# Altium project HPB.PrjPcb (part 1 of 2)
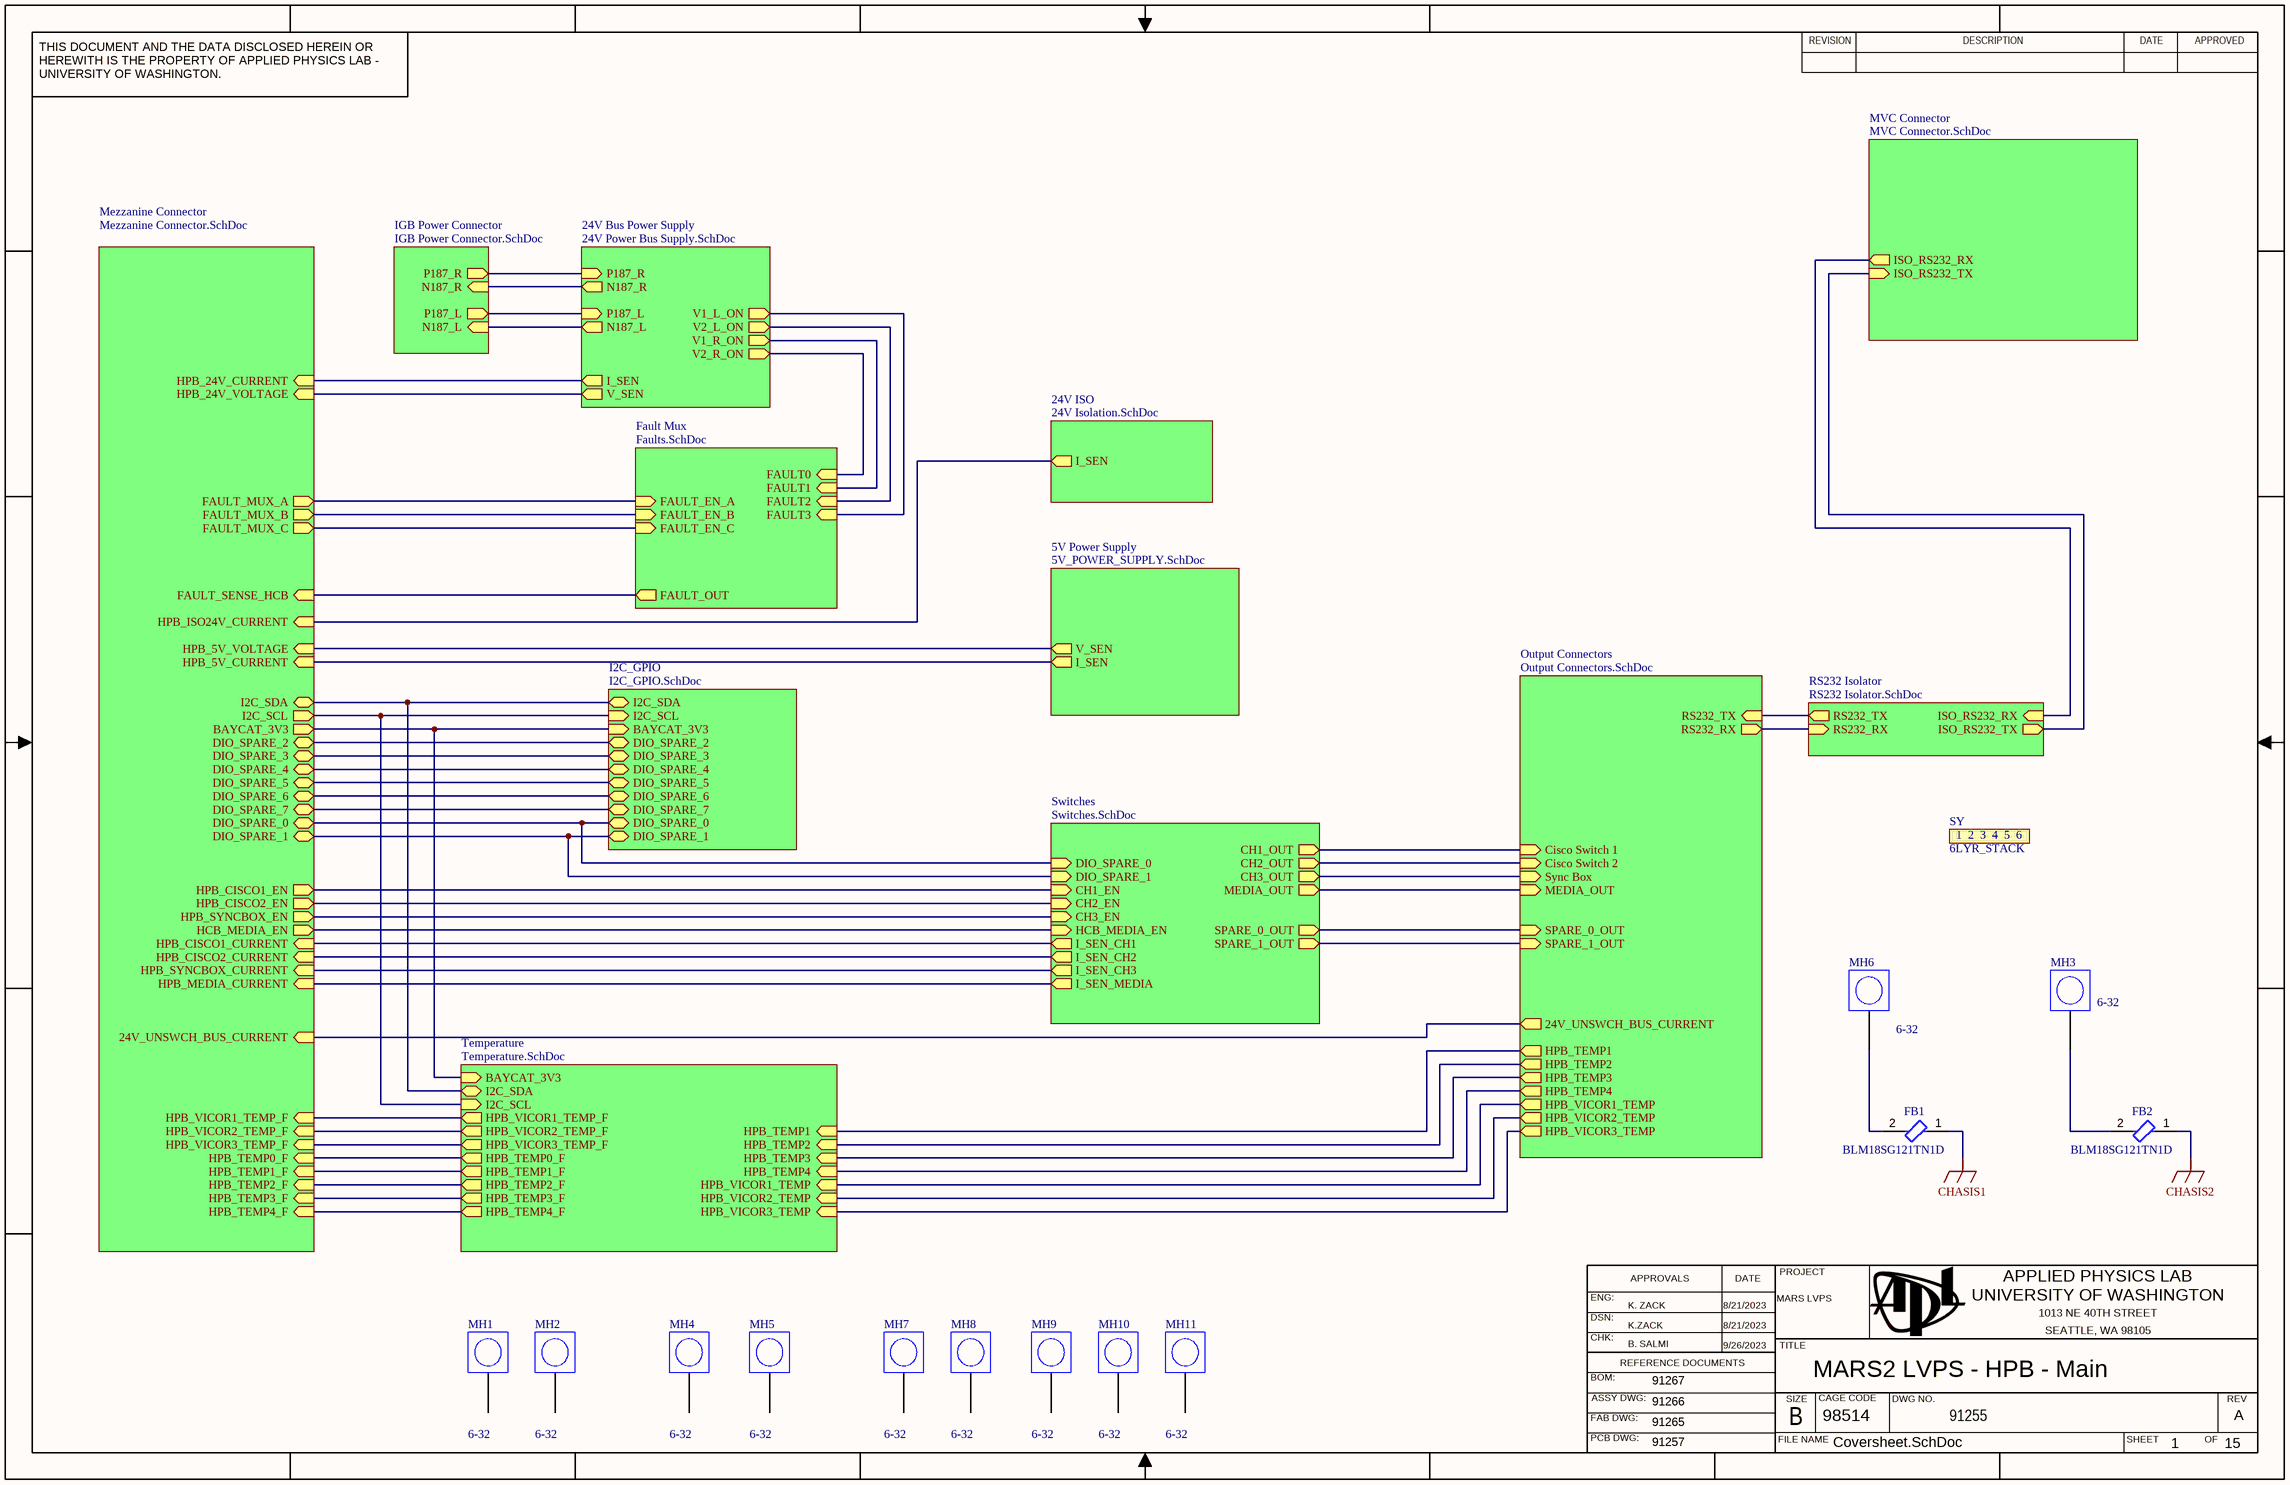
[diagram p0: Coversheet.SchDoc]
Gbl_Cage: 98514; Gbl_CheckedBy: B. SALMI; Gbl_CHK_APP_DATE: 9/26/2023; Gbl_DOC_NO_ASSY_DWG: 91266; Gbl_DOC_NO_BOM: 91267; Gbl_DOC_NO_FAB_DWG: 91265; Gbl_DOC_NO_SCH_DWG: 91255; Gbl_DrawnBy: K.ZACK; Gbl_DSN_APP_DATE: 8/21/2023; Gbl_ENG_APP_DATE: 8/21/2023; Gbl_Engineer: K. ZACK; Gbl_PCB_DWG_NO: 91257; Gbl_Project: MARS LVPS; Gbl_Revision: A
15 sheets, 321 parts. Net scope: hierarchical (ports join the sheet entries above them; power ports are global).
Board file: HPB.PcbDoc
Sheets:
  Coversheet.SchDoc
    IGB Power Connector = IGB Power Connector.SchDoc
    24V Bus Power Supply = 24V Power Bus Supply.SchDoc
      1.024V Comparator V1-Left = 1V024_Comparators.SchDoc
      1.024V Comparator V2-Left = 1V024_Comparators.SchDoc
      1.024V Comparator V1-Right = 1V024_Comparators.SchDoc
      1.024V Comparator V2-Right = 1V024_Comparators.SchDoc
    Mezzanine Connector = Mezzanine Connector.SchDoc
    24V ISO = 24V Isolation.SchDoc
    5V Power Supply = 5V_POWER_SUPPLY.SchDoc
    MVC Connector = MVC Connector.SchDoc
    Output Connectors = Output Connectors.SchDoc
    Fault Mux = Faults.SchDoc
    Switches = Switches.SchDoc
      . = P-CH_SWITCH.SchDoc
      . = P-CH_SWITCH.SchDoc
      . = P-CH_SWITCH.SchDoc
      . = P-CH_SWITCH.SchDoc
      . = P-CH_SWITCH.SchDoc
      . = P-CH_SWITCH.SchDoc
    RS232 Isolator = RS232 Isolator.SchDoc
    Temperature = Temperature.SchDoc
    I2C_GPIO = I2C_GPIO.SchDoc

## Sheet Coversheet.SchDoc: MARS2 LVPS - HPB - Main
size 431 x 279 mm; Organization: ORGANIZATION; Address1: APPLIED PHYSICS LAB; Address2: UNIVERSITY OF WASHINGTON; Address3: 1013 NE 40TH STREET; Address4: SEATTLE, WA 98105; DocumentNumber: 1; Revision: -; SheetNumber: 1; SheetTotal: 15; ENG_APP_DATE: --/--/--; DSN_APP_DATE: --/--/--; CHK_APP_DATE: --/--/--

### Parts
FB1  BLM18SG121TN1D  [FP-BLM18-0_15-t0_5-d1_2-IPC_B]
FB2  BLM18SG121TN1D  [FP-BLM18-0_15-t0_5-d1_2-IPC_B]
MH1  Fastener Size: 6-32  [MH-M3-Footprint-1 - Oversized MARS2]  (hidden comment: MH-MARS2-6-32)  (no BOM)
MH2  Fastener Size: 6-32  [MH-M3-Footprint-1 - Oversized MARS2]  (hidden comment: MH-MARS2-6-32)  (no BOM)
MH3  Fastener Size: 6-32  [MH-M3-Footprint-1 - Oversized MARS2]  (hidden comment: MH-MARS2-6-32)  (no BOM)
MH4  Fastener Size: 6-32  [MH-M3-Footprint-1 - Oversized MARS2]  (hidden comment: MH-MARS2-6-32)  (no BOM)
MH5  Fastener Size: 6-32  [MH-M3-Footprint-1 - Oversized MARS2]  (hidden comment: MH-MARS2-6-32)  (no BOM)
MH6  Fastener Size: 6-32  [MH-M3-Footprint-1 - Oversized MARS2]  (hidden comment: MH-MARS2-6-32)  (no BOM)
MH7  Fastener Size: 6-32  [MH-M3-Footprint-1 - Oversized MARS2]  (hidden comment: MH-MARS2-6-32)  (no BOM)
MH8  Fastener Size: 6-32  [MH-M3-Footprint-1 - Oversized MARS2]  (hidden comment: MH-MARS2-6-32)  (no BOM)
MH9  Fastener Size: 6-32  [MH-M3-Footprint-1 - Oversized MARS2]  (hidden comment: MH-MARS2-6-32)  (no BOM)
MH10  Fastener Size: 6-32  [MH-M3-Footprint-1 - Oversized MARS2]  (hidden comment: MH-MARS2-6-32)  (no BOM)
MH11  Fastener Size: 6-32  [MH-M3-Footprint-1 - Oversized MARS2]  (hidden comment: MH-MARS2-6-32)  (no BOM)
SY  6LYR_STACK  [6LYR_STACK-Footprint-1]

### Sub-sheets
5V Power Supply = 5V_POWER_SUPPLY.SchDoc: V_SEN (out), I_SEN (out)
24V Bus Power Supply = 24V Power Bus Supply.SchDoc: P187_L (in), N187_R (out), P187_R (in), N187_L (out), I_SEN (out), V_SEN (out), V1_L_ON (out), V2_L_ON (out), V1_R_ON (out), V2_R_ON (out)
24V ISO = 24V Isolation.SchDoc: I_SEN (out)
Fault Mux = Faults.SchDoc: FAULT_EN_C (in), FAULT_OUT (out), FAULT_EN_A (in), FAULT0 (in), FAULT_EN_B (in), FAULT1 (in), FAULT2 (in), FAULT3 (in)
I2C_GPIO = I2C_GPIO.SchDoc: I2C_SDA (bidir), I2C_SCL (in), DIO_SPARE_0 (bidir), DIO_SPARE_1 (bidir), DIO_SPARE_2 (bidir), DIO_SPARE_3 (bidir), DIO_SPARE_4 (bidir), DIO_SPARE_5 (bidir), DIO_SPARE_6 (bidir), DIO_SPARE_7 (bidir), BAYCAT_3V3 (in)
IGB Power Connector = IGB Power Connector.SchDoc: N187_R (in), P187_L (out), P187_R (out), N187_L (in)
Mezzanine Connector = Mezzanine Connector.SchDoc: HPB_VICOR1_TEMP_F (in), HPB_CISCO2_CURRENT (in), HPB_VICOR2_TEMP_F (in), HPB_TEMP0_F (in), HPB_24V_CURRENT (in), HPB_TEMP2_F (in), HPB_CISCO1_EN (out), HPB_CISCO1_CURRENT (in), FAULT_MUX_A (out), HPB_CISCO2_EN (out), HPB_SYNCBOX_CURRENT (in), HPB_VICOR3_TEMP_F (in), HPB_ISO24V_CURRENT (in), HPB_TEMP1_F (in), HPB_SYNCBOX_EN (out), FAULT_MUX_B (out), HPB_24V_VOLTAGE (in), HPB_5V_VOLTAGE (in), FAULT_MUX_C (out), HPB_TEMP4_F (in), HPB_5V_CURRENT (in), HPB_TEMP3_F (in), FAULT_SENSE_HCB (in), 24V_UNSWCH_BUS_CURRENT (in), DIO_SPARE_0 (bidir), DIO_SPARE_1 (bidir), DIO_SPARE_2 (bidir), DIO_SPARE_3 (bidir), DIO_SPARE_4 (bidir), DIO_SPARE_5 (bidir), DIO_SPARE_6 (bidir), DIO_SPARE_7 (bidir), HCB_MEDIA_EN (out), I2C_SCL (out), I2C_SDA (bidir), BAYCAT_3V3 (out), HPB_MEDIA_CURRENT (in)
MVC Connector = MVC Connector.SchDoc: ISO_RS232_TX (in), ISO_RS232_RX (out)
Output Connectors = Output Connectors.SchDoc: Cisco Switch 1 (in), Cisco Switch 2 (in), Sync Box (in), RS232_TX (in), RS232_RX (out), HPB_TEMP4 (out), HPB_TEMP1 (out), HPB_TEMP2 (out), HPB_TEMP3 (out), HPB_VICOR1_TEMP (out), HPB_VICOR2_TEMP (out), HPB_VICOR3_TEMP (out), 24V_UNSWCH_BUS_CURRENT (out), MEDIA_OUT (in), SPARE_0_OUT (in), SPARE_1_OUT (in)
RS232 Isolator = RS232 Isolator.SchDoc: RS232_RX (in), RS232_TX (out), ISO_RS232_TX (out), ISO_RS232_RX (in)
Switches = Switches.SchDoc: CH3_OUT (out), CH2_EN (in), CH1_OUT (out), I_SEN_CH2 (out), I_SEN_CH1 (out), CH3_EN (in), I_SEN_CH3 (out), CH1_EN (in), CH2_OUT (out), DIO_SPARE_0 (in), DIO_SPARE_1 (in), HCB_MEDIA_EN (in), MEDIA_OUT (out), SPARE_0_OUT (out), SPARE_1_OUT (out), I_SEN_MEDIA (out)
Temperature = Temperature.SchDoc: HPB_VICOR2_TEMP_F (out), HPB_TEMP0_F (out), HPB_TEMP1_F (out), HPB_VICOR1_TEMP_F (out), HPB_TEMP2_F (out), HPB_TEMP4_F (out), HPB_TEMP3_F (out), HPB_VICOR3_TEMP_F (out), HPB_TEMP4 (in), HPB_TEMP1 (in), HPB_TEMP2 (in), HPB_TEMP3 (in), HPB_VICOR1_TEMP (in), HPB_VICOR2_TEMP (in), HPB_VICOR3_TEMP (in), BAYCAT_3V3 (in), I2C_SDA (bidir), I2C_SCL (in)

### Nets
CHASIS1: FB1.1
CHASIS2: FB2.1
24V_UNSWCH_BUS_CURRENT: sheet Mezzanine Connector/24V_UNSWCH_BUS_CURRENT, sheet Output Connectors/24V_UNSWCH_BUS_CURRENT
BAYCAT_3V3: sheet Mezzanine Connector/BAYCAT_3V3, sheet Temperature/BAYCAT_3V3, sheet I2C_GPIO/BAYCAT_3V3
DIO_SPARE_0: sheet Mezzanine Connector/DIO_SPARE_0, sheet Switches/DIO_SPARE_0, sheet I2C_GPIO/DIO_SPARE_0
DIO_SPARE_1: sheet Mezzanine Connector/DIO_SPARE_1, sheet Switches/DIO_SPARE_1, sheet I2C_GPIO/DIO_SPARE_1
DIO_SPARE_2: sheet Mezzanine Connector/DIO_SPARE_2, sheet I2C_GPIO/DIO_SPARE_2
DIO_SPARE_3: sheet Mezzanine Connector/DIO_SPARE_3, sheet I2C_GPIO/DIO_SPARE_3
DIO_SPARE_4: sheet Mezzanine Connector/DIO_SPARE_4, sheet I2C_GPIO/DIO_SPARE_4
DIO_SPARE_5: sheet Mezzanine Connector/DIO_SPARE_5, sheet I2C_GPIO/DIO_SPARE_5
DIO_SPARE_6: sheet Mezzanine Connector/DIO_SPARE_6, sheet I2C_GPIO/DIO_SPARE_6
DIO_SPARE_7: sheet Mezzanine Connector/DIO_SPARE_7, sheet I2C_GPIO/DIO_SPARE_7
FAULT_MUX_A: sheet Mezzanine Connector/FAULT_MUX_A, sheet Fault Mux/FAULT_EN_A
FAULT_MUX_B: sheet Mezzanine Connector/FAULT_MUX_B, sheet Fault Mux/FAULT_EN_B
FAULT_MUX_C: sheet Mezzanine Connector/FAULT_MUX_C, sheet Fault Mux/FAULT_EN_C
FAULT_SENSE_HCB: sheet Mezzanine Connector/FAULT_SENSE_HCB, sheet Fault Mux/FAULT_OUT
HCB_MEDIA_EN: sheet Mezzanine Connector/HCB_MEDIA_EN, sheet Switches/HCB_MEDIA_EN
HPB_5V_CURRENT: sheet Mezzanine Connector/HPB_5V_CURRENT, sheet 5V Power Supply/I_SEN
HPB_5V_VOLTAGE: sheet Mezzanine Connector/HPB_5V_VOLTAGE, sheet 5V Power Supply/V_SEN
HPB_24V_CURRENT: sheet 24V Bus Power Supply/I_SEN, sheet Mezzanine Connector/HPB_24V_CURRENT
HPB_24V_VOLTAGE: sheet 24V Bus Power Supply/V_SEN, sheet Mezzanine Connector/HPB_24V_VOLTAGE
HPB_CISCO1_CURRENT: sheet Mezzanine Connector/HPB_CISCO1_CURRENT, sheet Switches/I_SEN_CH1
HPB_CISCO1_EN: sheet Mezzanine Connector/HPB_CISCO1_EN, sheet Switches/CH1_EN
HPB_CISCO2_CURRENT: sheet Mezzanine Connector/HPB_CISCO2_CURRENT, sheet Switches/I_SEN_CH2
HPB_CISCO2_EN: sheet Mezzanine Connector/HPB_CISCO2_EN, sheet Switches/CH2_EN
HPB_ISO24V_CURRENT: sheet Mezzanine Connector/HPB_ISO24V_CURRENT, sheet 24V ISO/I_SEN
HPB_MEDIA_CURRENT: sheet Mezzanine Connector/HPB_MEDIA_CURRENT, sheet Switches/I_SEN_MEDIA
HPB_SYNCBOX_CURRENT: sheet Mezzanine Connector/HPB_SYNCBOX_CURRENT, sheet Switches/I_SEN_CH3
HPB_SYNCBOX_EN: sheet Mezzanine Connector/HPB_SYNCBOX_EN, sheet Switches/CH3_EN
HPB_TEMP0: sheet Mezzanine Connector/HPB_TEMP0_F, sheet Temperature/HPB_TEMP0_F
HPB_TEMP1: sheet Mezzanine Connector/HPB_TEMP1_F, sheet Temperature/HPB_TEMP1_F
HPB_TEMP2: sheet Mezzanine Connector/HPB_TEMP2_F, sheet Temperature/HPB_TEMP2_F
HPB_TEMP3: sheet Mezzanine Connector/HPB_TEMP3_F, sheet Temperature/HPB_TEMP3_F
HPB_TEMP4: sheet Mezzanine Connector/HPB_TEMP4_F, sheet Temperature/HPB_TEMP4_F
HPB_VICOR1_TEMP: sheet Mezzanine Connector/HPB_VICOR1_TEMP_F, sheet Temperature/HPB_VICOR1_TEMP_F
HPB_VICOR2_TEMP: sheet Mezzanine Connector/HPB_VICOR2_TEMP_F, sheet Temperature/HPB_VICOR2_TEMP_F
HPB_VICOR3_TEMP: sheet Mezzanine Connector/HPB_VICOR3_TEMP_F, sheet Temperature/HPB_VICOR3_TEMP_F
I2C_SCL: sheet Mezzanine Connector/I2C_SCL, sheet Temperature/I2C_SCL, sheet I2C_GPIO/I2C_SCL
I2C_SDA: sheet Mezzanine Connector/I2C_SDA, sheet Temperature/I2C_SDA, sheet I2C_GPIO/I2C_SDA
N187_L: sheet IGB Power Connector/N187_L, sheet 24V Bus Power Supply/N187_L
N187_R: sheet IGB Power Connector/N187_R, sheet 24V Bus Power Supply/N187_R
OUT: sheet 24V Bus Power Supply/V1_L_ON, sheet Fault Mux/FAULT3
OUT: sheet 24V Bus Power Supply/V2_L_ON, sheet Fault Mux/FAULT2  [a separate net that carries the same name]
OUT: sheet 24V Bus Power Supply/V1_R_ON, sheet Fault Mux/FAULT1  [a separate net that carries the same name]
OUT: sheet 24V Bus Power Supply/V2_R_ON, sheet Fault Mux/FAULT0  [a separate net that carries the same name]
P187_L: sheet IGB Power Connector/P187_L, sheet 24V Bus Power Supply/P187_L
P187_R: sheet IGB Power Connector/P187_R, sheet 24V Bus Power Supply/P187_R
NetFB1_2: FB1.2 MH6.1
NetFB2_2: FB2.2 MH3.1
NetJ5_3: sheet MVC Connector/ISO_RS232_RX, sheet RS232 Isolator/ISO_RS232_RX
NetJ5_6: sheet MVC Connector/ISO_RS232_TX, sheet RS232 Isolator/ISO_RS232_TX
NetJ6_1: sheet Output Connectors/RS232_RX, sheet RS232 Isolator/RS232_RX
NetJ6_3: sheet Output Connectors/RS232_TX, sheet RS232 Isolator/RS232_TX
NetJ8_1: sheet Output Connectors/Cisco Switch 1, sheet Switches/CH1_OUT
NetJ10_1: sheet Output Connectors/HPB_VICOR1_TEMP, sheet Temperature/HPB_VICOR1_TEMP
NetJ10_2: sheet Output Connectors/HPB_VICOR2_TEMP, sheet Temperature/HPB_VICOR2_TEMP
NetJ10_3: sheet Output Connectors/HPB_VICOR3_TEMP, sheet Temperature/HPB_VICOR3_TEMP
NetJ10_4: sheet Output Connectors/HPB_TEMP1, sheet Temperature/HPB_TEMP1
NetJ10_5: sheet Output Connectors/HPB_TEMP2, sheet Temperature/HPB_TEMP2
NetJ10_6: sheet Output Connectors/HPB_TEMP3, sheet Temperature/HPB_TEMP3
NetJ10_7: sheet Output Connectors/HPB_TEMP4, sheet Temperature/HPB_TEMP4
NetJ11_1: sheet Output Connectors/Cisco Switch 2, sheet Switches/CH2_OUT
NetJ13_1: sheet Output Connectors/Sync Box, sheet Switches/CH3_OUT
NetJ15_1: sheet Output Connectors/MEDIA_OUT, sheet Switches/MEDIA_OUT
NetJ16_1: sheet Output Connectors/SPARE_0_OUT, sheet Switches/SPARE_0_OUT
NetJ16_2: sheet Output Connectors/SPARE_1_OUT, sheet Switches/SPARE_1_OUT

Not connected (* = marked no-connect by the designer): MH1 1; MH2 1; MH4 1; MH5 1; MH7 1; MH8 1; MH9 1; MH10 1; MH11 1

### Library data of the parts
FB1 FB2 = CMP-00000-1: Ferrite Beads Multi-Layer 120Ohm 25% 100MHz 3A 0.025Ohm DCR 0603 T/R; DC Resistance (DCR): 25mR; Number of Circuits: 1; Shielding: Unshielded; Material: Steel,Ferrite; Impedance: 120R
MH1-MH11 = CMP-00028-00015-1: MARS2 Project 6-32 Mounting Hole Plated .; Plated: Yes
SY = CMP-00028-00011-3: Layer Indicator for 6 layer board

## Sheet IGB Power Connector.SchDoc: MARS2 LVPS - HPB - IGB PWR CONN
size 431 x 279 mm; Organization: ORGANIZATION; Address1: APPLIED PHYSICS LAB; Address2: UNIVERSITY OF WASHINGTON; Address3: 1013 NE 40TH STREET; Address4: SEATTLE, WA 98105; DocumentNumber: 3; Revision: -; SheetNumber: 3; SheetTotal: 15; ENG_APP_DATE: --/--/--; DSN_APP_DATE: --/--/--; CHK_APP_DATE: --/--/--
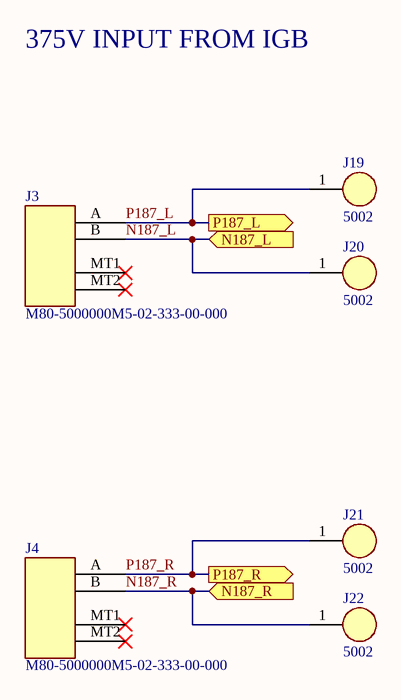
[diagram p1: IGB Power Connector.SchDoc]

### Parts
J3  M80-5000000M5-02-333-00-000  [FP-M80-5000000M5-02-333-0-MFG]
J4  M80-5000000M5-02-333-00-000  [FP-M80-5000000M5-02-333-0-MFG]
J19  5002  [FP-5002-MFG]
J20  5002  [FP-5002-MFG]
J21  5002  [FP-5002-MFG]
J22  5002  [FP-5002-MFG]

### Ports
N187_L (in), N187_R (in), P187_L (out), P187_R (out)

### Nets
N187_L: J3.B J20.1 ; port N187_L
N187_R: J4.B J22.1 ; port N187_R
P187_L: J3.A J19.1 ; port P187_L
P187_R: J4.A J21.1 ; port P187_R

Not connected (* = marked no-connect by the designer): J3 MT1(MNT_1)* MT2(MNT_2)*; J4 MT1(MNT_1)* MT2(MNT_2)*

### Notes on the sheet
- 375V INPUT FROM IGB

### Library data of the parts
J3 J4 = CMP-002-00075-3: Conn Header R/a 2POS 4MM; Manufacturer: Harwin; Number of Positions: 2; Pitch: 4.00mm; Current Rating: 40A; Contact Resistance: 25mR; Voltage Rating: 800V; Gender: Male; Insulation Resistance: 100MR
J19-J22 = CMP-002-00083-3: TEST POINT PC MINI .040D WHITE; Body Material: Bronze

## Sheet 24V Power Bus Supply.SchDoc: MARS2 LVPS - HPB - 375V to 24V PSU
size 431 x 279 mm; Organization: ORGANIZATION; Address1: APPLIED PHYSICS LAB; Address2: UNIVERSITY OF WASHINGTON; Address3: 1013 NE 40TH STREET; Address4: SEATTLE, WA 98105; DocumentNumber: 4; Revision: -; SheetNumber: 4; SheetTotal: 15; ENG_APP_DATE: --/--/--; DSN_APP_DATE: --/--/--; CHK_APP_DATE: --/--/--
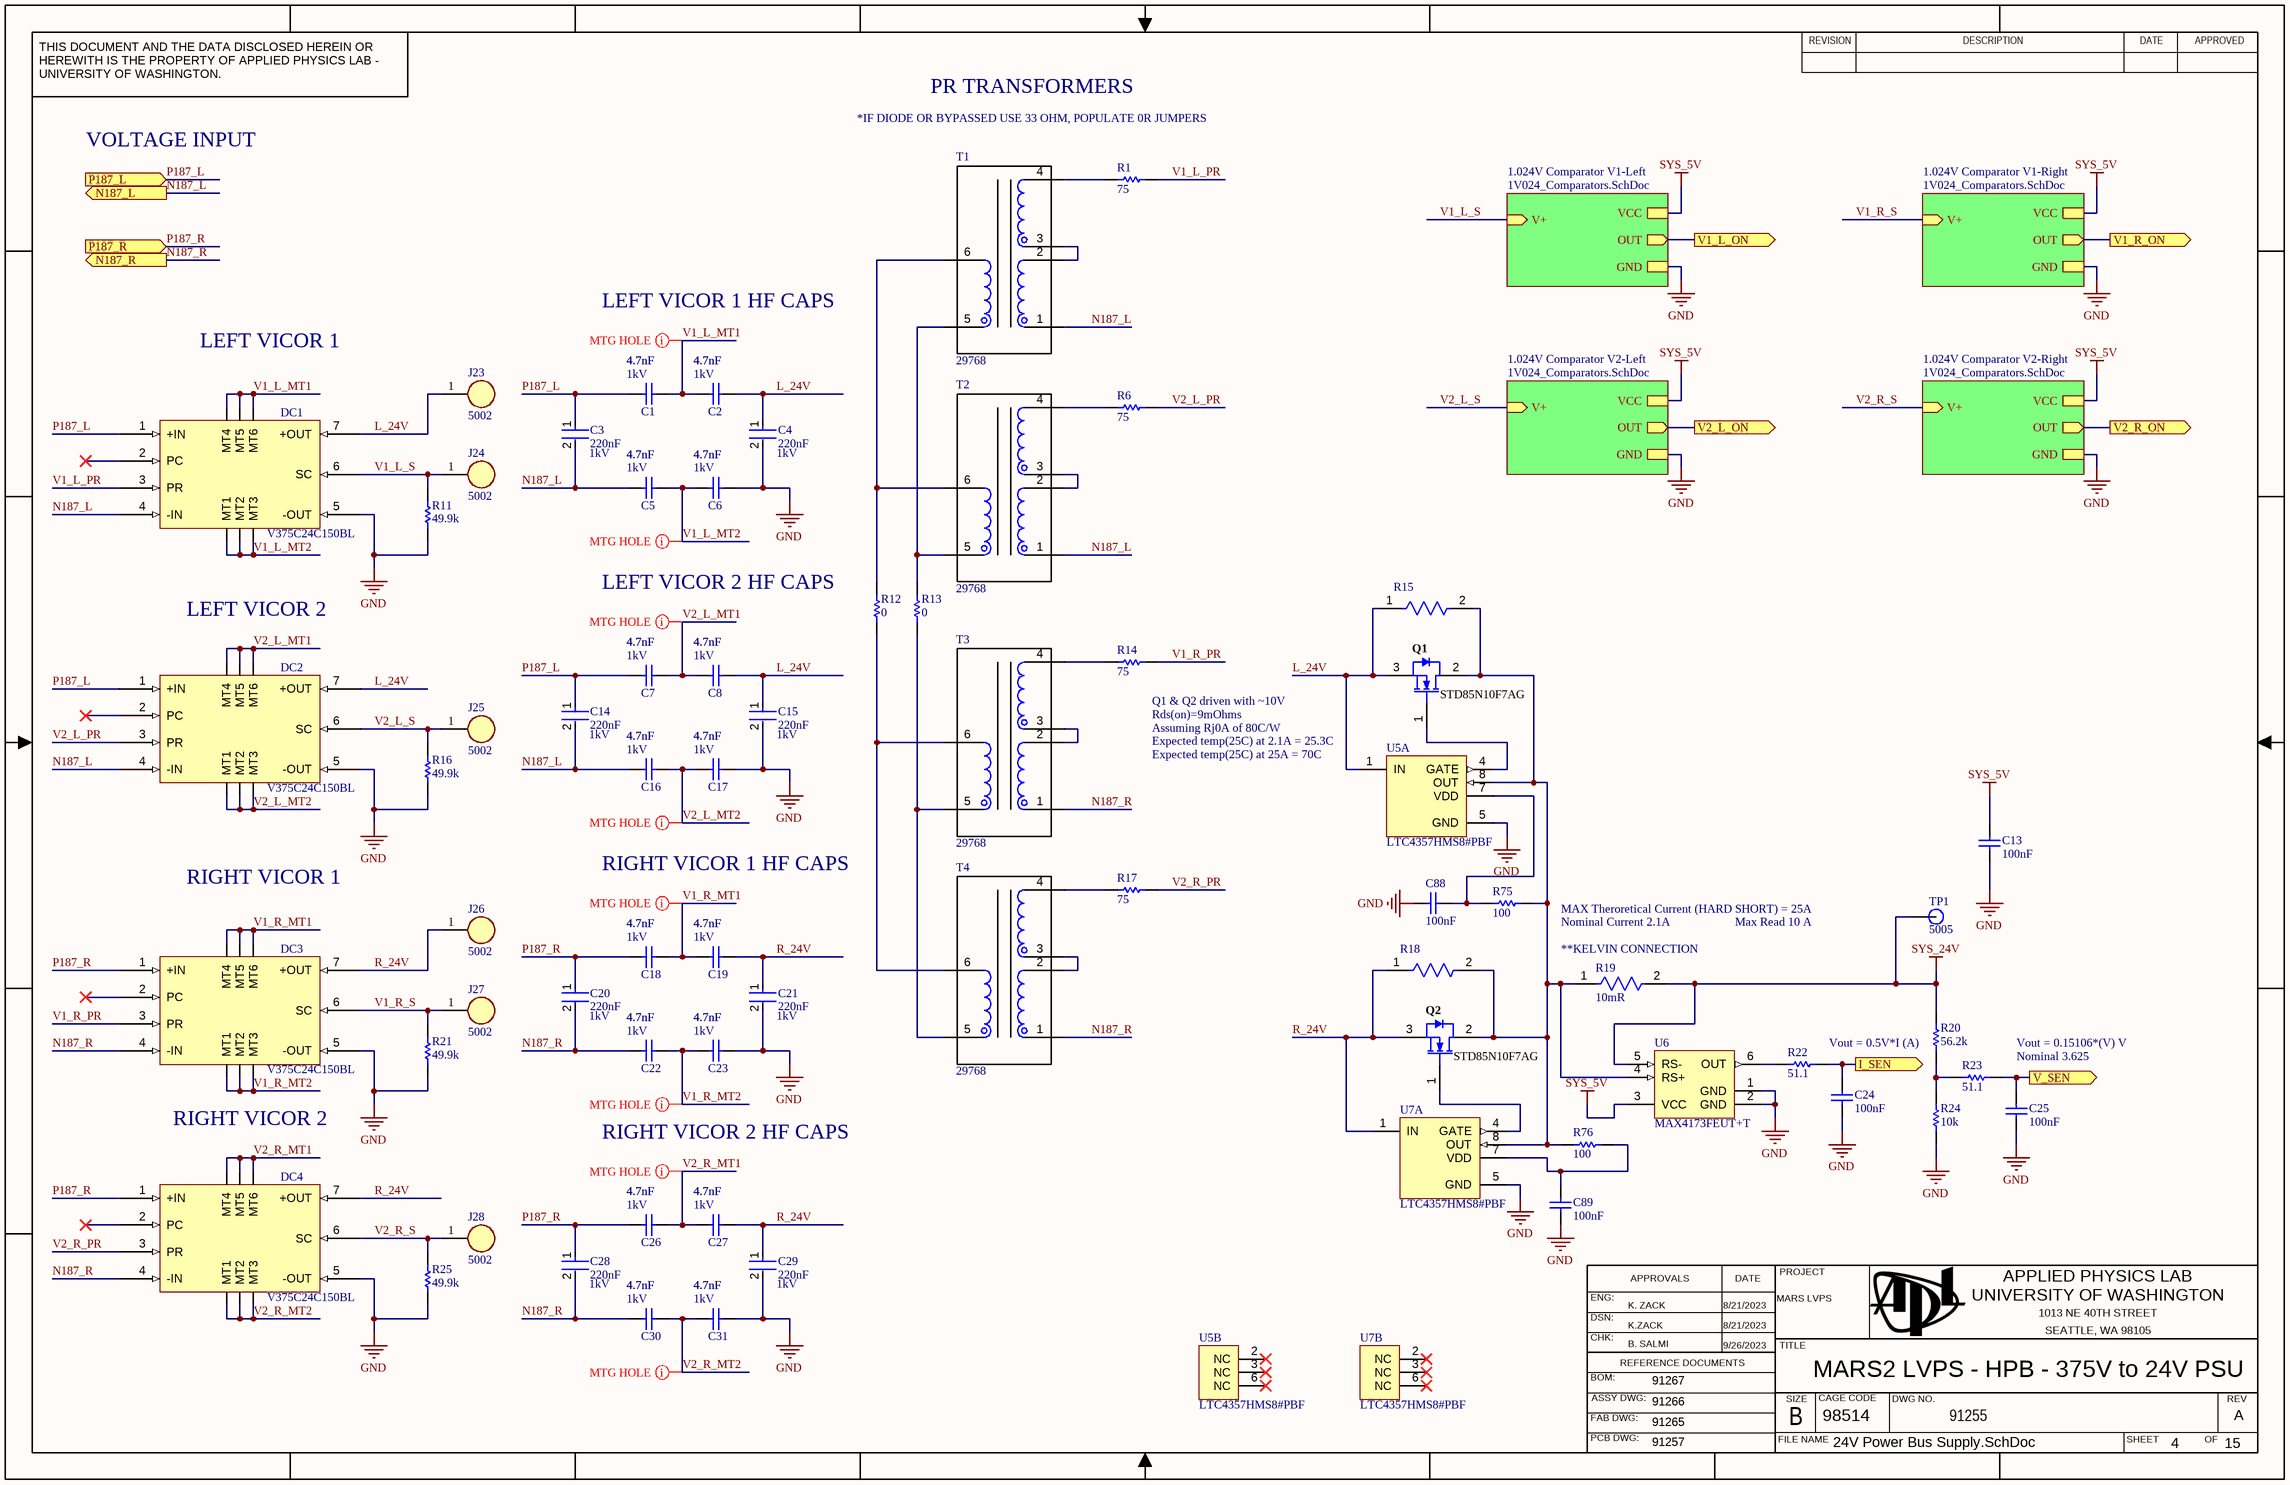
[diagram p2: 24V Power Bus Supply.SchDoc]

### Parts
C1  value 4.7nF  Capacitance: 4.7nF  Voltage Rating: 1kV  [CAPC2013X145X50NL20T25]  (hidden comment: Capacitor 4.7nF 10%, 1kV, X7R, 0805)
C2  value 4.7nF  Capacitance: 4.7nF  Voltage Rating: 1kV  [CAPC2013X145X50NL20T25]  (hidden comment: Capacitor 4.7nF 10%, 1kV, X7R, 0805)
C3  value 220nF  Voltage Rating (DC): 1kV  [FP-RDEUE1+0_5-MFG]  (hidden comment: Capacitor 0.22uF, 20%, 1kV,X7R,Radial)
C4  value 220nF  Voltage Rating (DC): 1kV  [FP-RDEUE1+0_5-MFG]  (hidden comment: Capacitor 0.22uF, 20%, 1kV,X7R,Radial)
C5  value 4.7nF  Capacitance: 4.7nF  Voltage Rating: 1kV  [CAPC2013X145X50NL20T25]  (hidden comment: Capacitor 4.7nF 10%, 1kV, X7R, 0805)
C6  value 4.7nF  Capacitance: 4.7nF  Voltage Rating: 1kV  [CAPC2013X145X50NL20T25]  (hidden comment: Capacitor 4.7nF 10%, 1kV, X7R, 0805)
C7  value 4.7nF  Capacitance: 4.7nF  Voltage Rating: 1kV  [CAPC2013X145X50NL20T25]  (hidden comment: Capacitor 4.7nF 10%, 1kV, X7R, 0805)
C8  value 4.7nF  Capacitance: 4.7nF  Voltage Rating: 1kV  [CAPC2013X145X50NL20T25]  (hidden comment: Capacitor 4.7nF 10%, 1kV, X7R, 0805)
C13  value 100nF  [CAPC1608X90X40NL10T20]  (hidden comment: Capacitor 100 nF +/-10% 50 V 0603)
C14  value 220nF  Voltage Rating (DC): 1kV  [FP-RDEUE1+0_5-MFG]  (hidden comment: Capacitor 0.22uF, 20%, 1kV,X7R,Radial)
C15  value 220nF  Voltage Rating (DC): 1kV  [FP-RDEUE1+0_5-MFG]  (hidden comment: Capacitor 0.22uF, 20%, 1kV,X7R,Radial)
C16  value 4.7nF  Capacitance: 4.7nF  Voltage Rating: 1kV  [CAPC2013X145X50NL20T25]  (hidden comment: Capacitor 4.7nF 10%, 1kV, X7R, 0805)
C17  value 4.7nF  Capacitance: 4.7nF  Voltage Rating: 1kV  [CAPC2013X145X50NL20T25]  (hidden comment: Capacitor 4.7nF 10%, 1kV, X7R, 0805)
C18  value 4.7nF  Capacitance: 4.7nF  Voltage Rating: 1kV  [CAPC2013X145X50NL20T25]  (hidden comment: Capacitor 4.7nF 10%, 1kV, X7R, 0805)
C19  value 4.7nF  Capacitance: 4.7nF  Voltage Rating: 1kV  [CAPC2013X145X50NL20T25]  (hidden comment: Capacitor 4.7nF 10%, 1kV, X7R, 0805)
C20  value 220nF  Voltage Rating (DC): 1kV  [FP-RDEUE1+0_5-MFG]  (hidden comment: Capacitor 0.22uF, 20%, 1kV,X7R,Radial)
C21  value 220nF  Voltage Rating (DC): 1kV  [FP-RDEUE1+0_5-MFG]  (hidden comment: Capacitor 0.22uF, 20%, 1kV,X7R,Radial)
C22  value 4.7nF  Capacitance: 4.7nF  Voltage Rating: 1kV  [CAPC2013X145X50NL20T25]  (hidden comment: Capacitor 4.7nF 10%, 1kV, X7R, 0805)
C23  value 4.7nF  Capacitance: 4.7nF  Voltage Rating: 1kV  [CAPC2013X145X50NL20T25]  (hidden comment: Capacitor 4.7nF 10%, 1kV, X7R, 0805)
C24  value 100nF  [CAPC1608X90X40NL10T20]  (hidden comment: Capacitor 100 nF +/-10% 50 V 0603)
C25  value 100nF  [CAPC1608X90X40NL10T20]  (hidden comment: Capacitor 100 nF +/-10% 50 V 0603)
C26  value 4.7nF  Capacitance: 4.7nF  Voltage Rating: 1kV  [CAPC2013X145X50NL20T25]  (hidden comment: Capacitor 4.7nF 10%, 1kV, X7R, 0805)
C27  value 4.7nF  Capacitance: 4.7nF  Voltage Rating: 1kV  [CAPC2013X145X50NL20T25]  (hidden comment: Capacitor 4.7nF 10%, 1kV, X7R, 0805)
C28  value 220nF  Voltage Rating (DC): 1kV  [FP-RDEUE1+0_5-MFG]  (hidden comment: Capacitor 0.22uF, 20%, 1kV,X7R,Radial)
C29  value 220nF  Voltage Rating (DC): 1kV  [FP-RDEUE1+0_5-MFG]  (hidden comment: Capacitor 0.22uF, 20%, 1kV,X7R,Radial)
C30  value 4.7nF  Capacitance: 4.7nF  Voltage Rating: 1kV  [CAPC2013X145X50NL20T25]  (hidden comment: Capacitor 4.7nF 10%, 1kV, X7R, 0805)
C31  value 4.7nF  Capacitance: 4.7nF  Voltage Rating: 1kV  [CAPC2013X145X50NL20T25]  (hidden comment: Capacitor 4.7nF 10%, 1kV, X7R, 0805)
C88  value 100nF  [CAPC1608X90X40NL10T20]  (hidden comment: Capacitor 100 nF +/-10% 50 V 0603)
C89  value 100nF  [CAPC1608X90X40NL10T20]  (hidden comment: Capacitor 100 nF +/-10% 50 V 0603)
DC1  V375C24C150BL  [V375C24C150BL-Footprint-1]
DC2  V375C24C150BL  [V375C24C150BL-Footprint-1]
DC3  V375C24C150BL  [V375C24C150BL-Footprint-1]
DC4  V375C24C150BL  [V375C24C150BL-Footprint-1]
J23  5002  [FP-5002-MFG]
J24  5002  [FP-5002-MFG]
J25  5002  [FP-5002-MFG]
J26  5002  [FP-5002-MFG]
J27  5002  [FP-5002-MFG]
J28  5002  [FP-5002-MFG]
Q1  STD85N10F7AG  [TO228P970-3N]
Q2  STD85N10F7AG  [TO228P970-3N]
R1  value 75  [RESC1609X50X30ML08T20]  (hidden comment: Resistor 75R0 +/-1% 0603 100 mW)
R6  value 75  [RESC1609X50X30ML08T20]  (hidden comment: Resistor 75R0 +/-1% 0603 100 mW)
R11  value 49.9k  [RESC1608X55X25ML10T15]  (hidden comment: Resistor 49K9 +/-1% 0603 100 mW)
R12  value 0  [RESC1608X55X25ML10T15]  (hidden comment: Resistor 0R +/- 5% 0603 100 mW)
R13  value 0  [RESC1608X55X25ML10T15]  (hidden comment: Resistor 0R +/- 5% 0603 100 mW)
R14  value 75  [RESC1609X50X30ML08T20]  (hidden comment: Resistor 75R0 +/-1% 0603 100 mW)
R15  Resistor 0R01 1% 1206 1W  [FP-WSLP1206-FP_1_65x1_93x-IPC_A]  (value not drawn)
R16  value 49.9k  [RESC1608X55X25ML10T15]  (hidden comment: Resistor 49K9 +/-1% 0603 100 mW)
R17  value 75  [RESC1609X50X30ML08T20]  (hidden comment: Resistor 75R0 +/-1% 0603 100 mW)
R18  Resistor 0R01 1% 1206 1W  [FP-WSLP1206-FP_1_65x1_93x-IPC_A]  (value not drawn)
R19  Resistance: 10mR  [FP-WSLP1206-FP_1_65x1_93x-IPC_A]  (hidden comment: Resistor 0R01 1% 1206 1W)
R20  value 56.2k  [RESC1608X55X25ML10T15]  (hidden comment: Resistor 56K2 +/-1% 0603 100 mW)
R21  value 49.9k  [RESC1608X55X25ML10T15]  (hidden comment: Resistor 49K9 +/-1% 0603 100 mW)
R22  value 51.1  [RESC1609X50X30ML08T20]  (hidden comment: Resistor 51R1 +/-1% 0603 100 mW)
R23  value 51.1  [RESC1609X50X30ML08T20]  (hidden comment: Resistor 51R1 +/-1% 0603 100 mW)
R24  value 10k  [RESC1608X55X25ML10T15]  (hidden comment: Resistor 10k +/-1% 0603 100 mW)
R25  value 49.9k  [RESC1608X55X25ML10T15]  (hidden comment: Resistor 49K9 +/-1% 0603 100 mW)
R75  value 100  [RESC1609X50X30ML08T20]  (hidden comment: Resistor 100R +/-1% 0603 100 mW)
R76  value 100  [RESC1609X50X30ML08T20]  (hidden comment: Resistor 100R +/-1% 0603 100 mW)
T1  29768  [29768-Footprint-1]
T2  29768  [29768-Footprint-1]
T3  29768  [29768-Footprint-1]
T4  29768  [29768-Footprint-1]
TP1  5005  [TestPoint-5005-Footprint-1]
U5  LTC4357HMS8#PBF  [LT-MS8-8_N]  (parts A,B of 2)
U6  MAX4173FEUT+T  [MAXM-U6+1_N]
U7  LTC4357HMS8#PBF  [LT-MS8-8_N]  (parts A,B of 2)

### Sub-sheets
1.024V Comparator V1-Left = 1V024_Comparators.SchDoc: V+ (in), VCC, GND, OUT (out)
1.024V Comparator V1-Right = 1V024_Comparators.SchDoc: V+ (in), VCC, GND, OUT (out)
1.024V Comparator V2-Left = 1V024_Comparators.SchDoc: V+ (in), VCC, GND, OUT (out)
1.024V Comparator V2-Right = 1V024_Comparators.SchDoc: V+ (in), VCC, GND, OUT (out)

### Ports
I_SEN (out), N187_L (out), N187_R (out), P187_L (in), P187_R (in), V1_L_ON (out), V1_R_ON (out), V2_L_ON (out), V2_R_ON (out), V_SEN (out)

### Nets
GND: C4.2 C6.2 C13.1 C15.2 C17.2 C21.2 C23.2 C24.1 C25.1 C29.2 C31.2 C88.1 C89.1 DC1.5(-OUT) DC2.5(-OUT) DC3.5(-OUT) DC4.5(-OUT) R11.2 R16.2 R21.2 R24.1 R25.2 U5.5(GND) U6.1(GND) U6.2(GND) U7.5(GND) ; sheet 1.024V Comparator V1-Left/GND, sheet 1.024V Comparator V2-Left/GND, sheet 1.024V Comparator V1-Right/GND, sheet 1.024V Comparator V2-Right/GND
SYS_5V: C13.2 U6.3(VCC) ; sheet 1.024V Comparator V1-Left/VCC, sheet 1.024V Comparator V2-Left/VCC, sheet 1.024V Comparator V1-Right/VCC, sheet 1.024V Comparator V2-Right/VCC  [project net VCC]
SYS_24V: R19.2 R20.2 TP1.1 U6.5(RS-)
HPB_24V_CURRENT: C24.2 R22.2 ; port I_SEN
HPB_24V_VOLTAGE: C25.2 R23.2 ; port V_SEN
L_24V: C2.2 C4.1 C8.2 C15.1 DC1.7(+OUT) DC2.7(+OUT) J23.1 Q1.3(S) R15.1 U5.1(IN)
N187_L: C3.2 C5.1 C14.2 C16.1 DC1.4(-IN) DC2.4(-IN) T1.1 T2.1 ; port N187_L
N187_R: C20.2 C22.1 C28.2 C30.1 DC3.4(-IN) DC4.4(-IN) T3.1 T4.1 ; port N187_R
OUT: port V1_L_ON, sheet 1.024V Comparator V1-Left/OUT
OUT: port V2_L_ON, sheet 1.024V Comparator V2-Left/OUT  [a separate net that carries the same name]
OUT: port V1_R_ON, sheet 1.024V Comparator V1-Right/OUT  [a separate net that carries the same name]
OUT: port V2_R_ON, sheet 1.024V Comparator V2-Right/OUT  [a separate net that carries the same name]
P187_L: C1.1 C3.1 C7.1 C14.1 DC1.1(+IN) DC2.1(+IN) ; port P187_L
P187_R: C18.1 C20.1 C26.1 C28.1 DC3.1(+IN) DC4.1(+IN) ; port P187_R
R_24V: C19.2 C21.1 C27.2 C29.1 DC3.7(+OUT) DC4.7(+OUT) J26.1 Q2.3(S) R18.1 U7.1(IN)
V1_L_MT1: C1.2 C2.1 DC1.MT4 DC1.MT5 DC1.MT6
V1_L_MT2: C5.2 C6.1 DC1.MT1 DC1.MT2 DC1.MT3
V1_L_PR: DC1.3(PR) R1.2
V1_L_S: DC1.6(SC) J24.1 R11.1 ; sheet 1.024V Comparator V1-Left/V+
V1_R_MT1: C18.2 C19.1 DC3.MT4 DC3.MT5 DC3.MT6
V1_R_MT2: C22.2 C23.1 DC3.MT1 DC3.MT2 DC3.MT3
V1_R_PR: DC3.3(PR) R14.2
V1_R_S: DC3.6(SC) J27.1 R21.1 ; sheet 1.024V Comparator V1-Right/V+
V2_L_MT1: C7.2 C8.1 DC2.MT4 DC2.MT5 DC2.MT6
V2_L_MT2: C16.2 C17.1 DC2.MT1 DC2.MT2 DC2.MT3
V2_L_PR: DC2.3(PR) R6.2
V2_L_S: DC2.6(SC) J25.1 R16.1 ; sheet 1.024V Comparator V2-Left/V+
V2_R_MT1: C26.2 C27.1 DC4.MT4 DC4.MT5 DC4.MT6
V2_R_MT2: C30.2 C31.1 DC4.MT1 DC4.MT2 DC4.MT3
V2_R_PR: DC4.3(PR) R17.2
V2_R_S: DC4.6(SC) J28.1 R25.1 ; sheet 1.024V Comparator V2-Right/V+
NetC88_2: C88.2 R75.1 U5.7(VDD)
NetC89_2: C89.2 R76.2 U7.7(VDD)
NetQ1_1: Q1.1(G) U5.4(GATE)
NetQ1_2: Q1.2(D) Q2.2(D) R15.2 R18.2 R19.1 R75.2 R76.1 U5.8(OUT) U6.4(RS+) U7.8(OUT)
NetQ2_1: Q2.1(G) U7.4(GATE)
NetR1_1: R1.1 T1.4
NetR6_1: R6.1 T2.4
NetR12_1: R12.1 T1.6 T2.6
NetR12_2: R12.2 T3.6 T4.6
NetR13_1: R13.1 T1.5 T2.5
NetR13_2: R13.2 T3.5 T4.5
NetR14_1: R14.1 T3.4
NetR17_1: R17.1 T4.4
NetR20_1: R20.1 R23.1 R24.2
NetR22_1: R22.1 U6.6(OUT)
NetT1_2: T1.2 T1.3
NetT2_2: T2.2 T2.3
NetT3_2: T3.2 T3.3
NetT4_2: T4.2 T4.3

Not connected (* = marked no-connect by the designer): DC1 2(PC)*; DC2 2(PC)*; DC3 2(PC)*; DC4 2(PC)*; U5 2(NC)* 3(NC)* 6(NC)*; U7 2(NC)* 3(NC)* 6(NC)*

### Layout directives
net class MTG Hole: V1_L_MT1, V1_L_MT2, V1_R_MT1, V1_R_MT2, V2_L_MT1, V2_L_MT2, V2_R_MT1, V2_R_MT2

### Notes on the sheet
- PR TRANSFORMERS
- VOLTAGE INPUT
- *IF DIODE OR BYPASSED USE 33 OHM, POPULATE 0R JUMPERS
- LEFT VICOR 1
- LEFT VICOR 1 HF CAPS
- LEFT VICOR 2
- LEFT VICOR 2 HF CAPS
- (near R14) Q1 & Q2 driven with
  0V
- (near R14) Rds(on)=9mOhms
- (near U5) Expected temp(25C) at 2.1A = 25.3C
- (near U5) Expected temp(25C) at 25A = 70C
- Assuming Rj0A of 80C/W
- RIGHT VICOR 1
- RIGHT VICOR 1 HF CAPS
- (near R19) **KELVIN CONNECTION
- (near R75) MAX Theroretical Current (HARD SHORT) = 25A
- Nominal Current 2.1A
- Max Read 10 A
- (near R20) Vout = 0.5V*I (A)
- Nominal 3.625
- Vout = 0.15106*(V) V
- RIGHT VICOR 2
- RIGHT VICOR 2 HF CAPS

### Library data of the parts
C1 C2 C5-C8 C16-C19 C22 C23 C26 C27 C30 C31 = CMP-001-00109-9: 0805 Arcshield HV 4.7nF Ceramic Multilayer Cap; 1000VDC; +125C; X7R Dielec; +/-10%; Decade: 1nF
C3 C4 C14 C15 C20 C21 C28 C29 = CMP-001-00084-11: Cap Ceramic 0.22uF 1000V X7R 20% Radial 5mm 125°C Bulk; Manufacturer PN: RDER73A224MUB1H03B; Lead Diameter: 0.5mm; Lead/Base Style: Straight; Decade: 100nF
C13 C24 C25 C88 C89 = CMP-001-00017-14: Chip Capacitor, 100 nF, +/- 10%, 50 V, 0603 (1608 Metric); Voltage Rating: 50V; Capacitor Type: Ceramic
DC1-DC4 = CMP-019-00060-1: 375C Series 150 W Single Output 24 V DC-DC Converter; Isolation Voltage: 3kV; Voltage - Output 1: 24V; Number of Outputs: 1; Max Output Current: 6.25A; Max Input Voltage: 425V; Max Power Dissipation: 150W; Efficiency: 86.5%; Isolation: Isolated; Min Input Voltage: 250V
J23-J28 = CMP-002-00083-3: as J19 on sheet IGB Power Connector
Q1 Q2 = CMP-013-00055-1: Trans MOSFET N-CH 100V 70A Automotive 3-Pin(2+Tab) DPAK T/R; Input Capacitance: 3.1nF; Max Power Dissipation: 85W; Rds On Max: 10mR
R1 R6 R14 R17 = CMP-009-01151-1: Chip Resistor, 75 Ohm, +/- 1%, 0.1 W, -55 to 155 degC, 0603 (1608 Metric); Voltage Rating: 75V; Power: 100mW; Decade: 10
R11 R16 R21 R25 = CMP-009-01001-3: Chip Resistor, 49.9k Ohm, +/- 1%, 0.1 W, -55 to 155 degC, 0603 (1608 Metric); Power: 100mW; Voltage Rating: 75V; Decade: 10k
R12 R13 = CMP-009-00006-6: Chip Resistor, 0 Ohm, 0.1 W, -55 to 155 degC, 0603 (1608 Metric); Voltage Rating: 50V; Power: 100mW
R15 R18 = CMP-009-01193-1: Res Metal Strip 1206 0.01 Ohm 1% 1W ±75ppm/°C Molded SMD SMD Embossed Plastic T/R; Manufacturer PN: WSLP1206R0100FEA; Resistance: 10mR
R19 = CMP-009-01193-1: Res Metal Strip 1206 0.01 Ohm 1% 1W ±75ppm/°C Molded SMD SMD Embossed Plastic T/R; Manufacturer PN: WSLP1206R0100FEA
R20 = CMP-009-01006-3: Chip Resistor, 56.2k Ohm, +/- 1%, 0.1 W, -55 to 155 degC, 0603 (1608 Metric); Voltage Rating: 75V; Power: 100mW; Decade: 10k
R22 R23 = CMP-009-01135-1: Chip Resistor, 51.1 Ohm, +/- 1%, 0.1 W, -55 to 155 degC, 0603 (1608 Metric); Voltage Rating: 75V; Power: 100mW; Decade: 10
R24 = CMP-009-00017-7: Chip Resistor, 10 KOhm, +/- 1%, 01 W, -55 to 155 degC, 0603 (1608 Metric); Voltage Rating: 50V; Power: 100mW
R75 R76 = CMP-009-01066-2: Chip Resistor, 100 Ohm, +/- 1%, 0.1 W, -55 to 155 degC, 0603 (1608 Metric); Voltage Rating: 75V; Power: 100mW
T1-T4 = CMP-012-00000-1: 3 W 101 to 187 uH 40 to 50 mOhm DCR PR Bus Toroidal Inductor; Manufacturer: Vicor; Lead/Base Style: PC Pin
TP1 = CMP-001-0000-5: PC TEST POINT COMPACT RED; Inside Diameter: 1.78mm; Hole Diameter: 1.6mm
U5 U7 = CMP-004-00036-2: OR Controller N+1 ORing Controller N-Channel N:1 8-MSOP; Min Supply Voltage: 9V; Max Output Current: 210uA; Max Supply Voltage: 80V
U6 = CMP-014-00007-3: MAX4173 Series 28 V 1.4 MHz Voltage Current Sense Operational Amplifier - SOT-23; Nominal Supply Current: 420uA; Common Mode Rejection Ratio: 90dB; Min Supply Voltage: 3V; Input Bias Current: 700uA; -3db Bandwidth: 1.4MHz; Max Supply Voltage: 28V; Max Supply Current: 1mA; Input Offset Voltage (Vos): 300uV; Gain: 50V/V

## Sheet 1V024_Comparators.SchDoc: MARS2 LVPS - HPB - Vicor Fault Mon
size 431 x 279 mm; Organization: ORGANIZATION; Address1: APPLIED PHYSICS LAB; Address2: UNIVERSITY OF WASHINGTON; Address3: 1013 NE 40TH STREET; Address4: SEATTLE, WA 98105; Revision: -; SheetNumber: 5; SheetTotal: 15; ENG_APP_DATE: --/--/--; DSN_APP_DATE: --/--/--; CHK_APP_DATE: --/--/--
Used 4 times, as channels 24V Bus Power Supply/1.024V Comparator V1-Left, 24V Bus Power Supply/1.024V Comparator V2-Left, 24V Bus Power Supply/1.024V Comparator V1-Right, 24V Bus Power Supply/1.024V Comparator V2-Right. Parts and nets are listed once, with the designators drawn on the sheet.
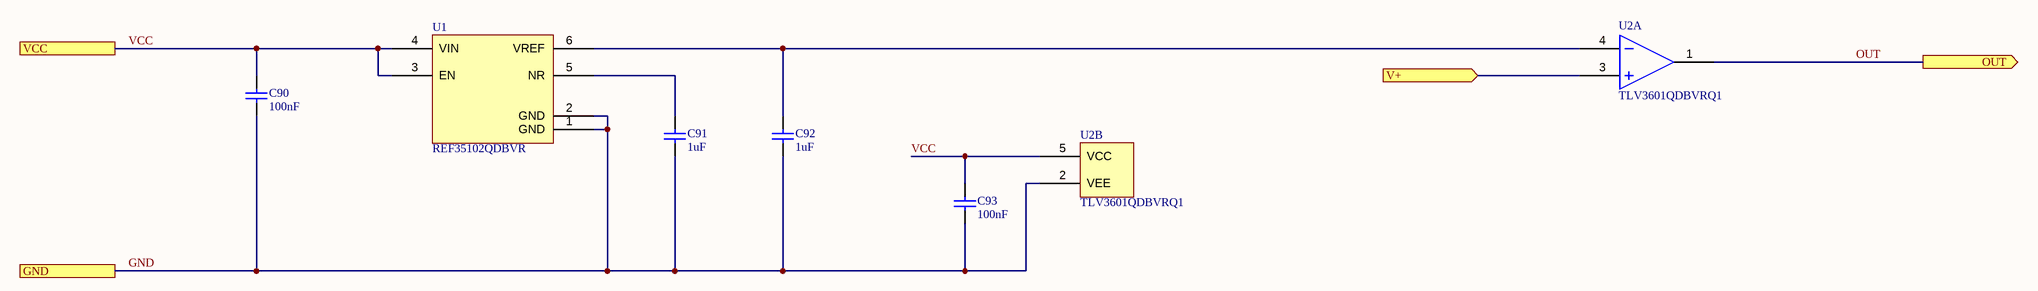
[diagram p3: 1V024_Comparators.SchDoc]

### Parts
C90  value 100nF  [CAPC1608X90X40NL10T20]  (hidden comment: Capacitor 100 nF +/-10% 50 V 0603)
C91  value 1uF  [CAPC3225X270X30ML30]  (hidden comment: Capacitor 1uF 10%, 50V, X7R, 1210)
C92  value 1uF  [CAPC3225X270X30ML30]  (hidden comment: Capacitor 1uF 10%, 50V, X7R, 1210)
C93  value 100nF  [CAPC1608X90X40NL10T20]  (hidden comment: Capacitor 100 nF +/-10% 50 V 0603)
U1  REF35102QDBVR  [SOT95P280X145-6M]
U2  TLV3601QDBVRQ1  [SOT95P280X145-5M]  (parts A,B of 2)

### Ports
GND, OUT (out), V+ (in), VCC

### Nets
GND: C90.1 C91.1 C92.1 C93.1 U1.1(GND) U1.2(GND) U2.2(VEE) ; port GND
OUT: U2.1(OUT) ; port OUT
V+: U2.3(IN+) ; port V+
VCC: C90.2 C93.2 U1.3(EN) U1.4(VIN) U2.5(VCC) ; port VCC
NetC91_2: C91.2 U1.5(NR)
NetC92_2: C92.2 U1.6(VREF) U2.4(IN-)

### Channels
24V Bus Power Supply/1.024V Comparator V1-Left: designators end in A; ports GND=GND OUT=OUT V+=V1_L_S VCC=VCC
24V Bus Power Supply/1.024V Comparator V2-Left: designators end in B; ports GND=GND OUT=OUT V+=V2_L_S VCC=VCC
24V Bus Power Supply/1.024V Comparator V1-Right: designators end in C; ports GND=GND OUT=OUT V+=V1_R_S VCC=VCC
24V Bus Power Supply/1.024V Comparator V2-Right: designators end in D; ports GND=GND OUT=OUT V+=V2_R_S VCC=VCC

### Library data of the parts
C90 C93 = CMP-001-00017-14: as C13 on sheet 24V Power Bus Supply
C91 C92 = CMP-001-00181-9: Chip Capacitor, 1uF, 10%, 50 V, X7R 1210 (3225 Metric); Capacitor Type: Ceramic
U1 = CMP-019-00086-3: 650-nA quiescent current, 12-ppm/°C drift, ultra-low-power precision voltage reference, 1.024V, 6-SOT-23 -40 to 125
U2 = CMP-014-00029-3: Automotive, 2.5-ns, high-speed, rail-to-rail comparator with push-pull outputs 5-SOT-23 -40 to 125

## Sheet Mezzanine Connector.SchDoc: MARS2 LVPS - HPB - Mezzanine Conn
size 431 x 279 mm; Organization: ORGANIZATION; Address1: APPLIED PHYSICS LAB; Address2: UNIVERSITY OF WASHINGTON; Address3: 1013 NE 40TH STREET; Address4: SEATTLE, WA 98105; DocumentNumber: 2; Revision: -; SheetNumber: 2; SheetTotal: 15; ENG_APP_DATE: --/--/--; DSN_APP_DATE: --/--/--; CHK_APP_DATE: --/--/--
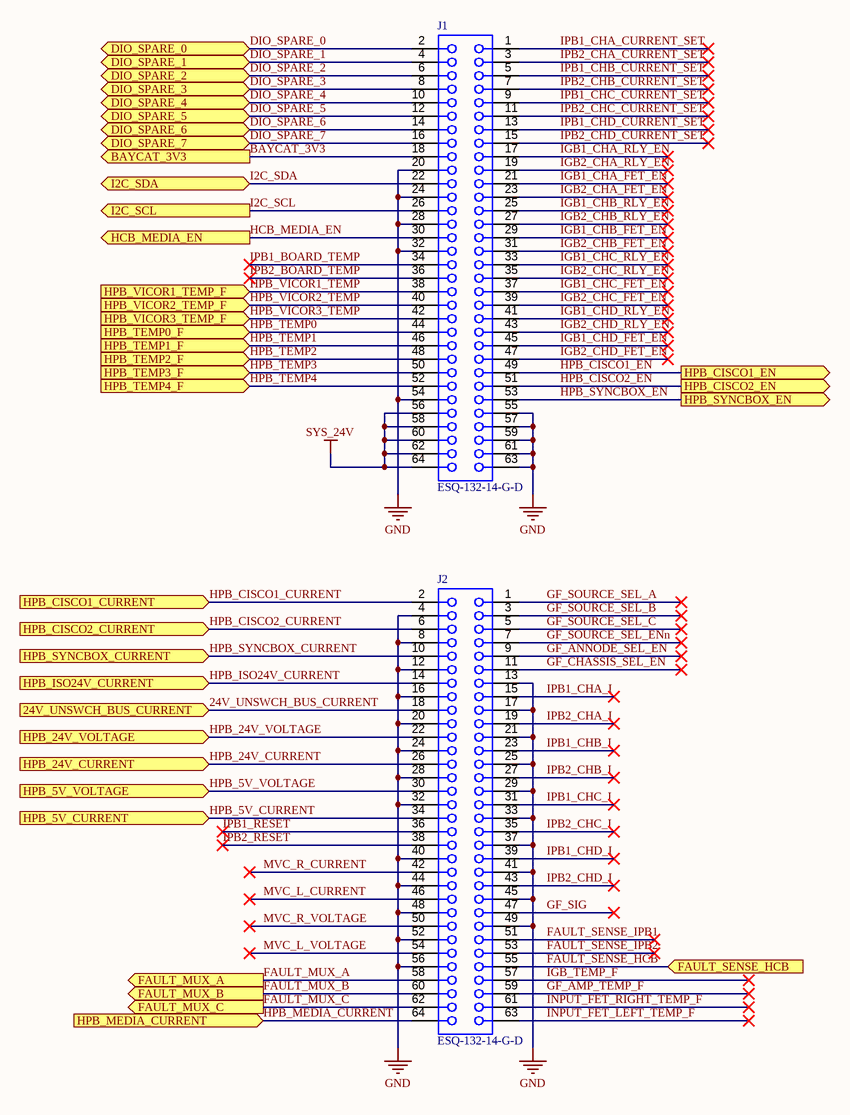
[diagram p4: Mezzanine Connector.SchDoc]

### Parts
J1  ESQ-132-14-G-D  [SMTC-ESQ-132-14-X-D]
J2  ESQ-132-14-G-D  [SMTC-ESQ-132-14-X-D]

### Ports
24V_UNSWCH_BUS_CURRENT (in), BAYCAT_3V3 (out), DIO_SPARE_0 (bidir), DIO_SPARE_1 (bidir), DIO_SPARE_2 (bidir), DIO_SPARE_3 (bidir), DIO_SPARE_4 (bidir), DIO_SPARE_5 (bidir), DIO_SPARE_6 (bidir), DIO_SPARE_7 (bidir), FAULT_MUX_A (out), FAULT_MUX_B (out), FAULT_MUX_C (out), FAULT_SENSE_HCB (in), HCB_MEDIA_EN (out), HPB_5V_CURRENT (in), HPB_5V_VOLTAGE (in), HPB_24V_CURRENT (in), HPB_24V_VOLTAGE (in), HPB_CISCO1_CURRENT (in), HPB_CISCO1_EN (out), HPB_CISCO2_CURRENT (in), HPB_CISCO2_EN (out), HPB_ISO24V_CURRENT (in), HPB_MEDIA_CURRENT (in), HPB_SYNCBOX_CURRENT (in), HPB_SYNCBOX_EN (out), HPB_TEMP0_F (in), HPB_TEMP1_F (in), HPB_TEMP2_F (in), HPB_TEMP3_F (in), HPB_TEMP4_F (in), HPB_VICOR1_TEMP_F (in), HPB_VICOR2_TEMP_F (in), HPB_VICOR3_TEMP_F (in), I2C_SCL (out), I2C_SDA (bidir)

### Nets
GND: J1.20 J1.24 J1.28 J1.32 J1.54 J1.55 J1.57 J1.59 J1.61 J1.63 J2.4 J2.8 J2.12 J2.13 J2.16 J2.17 J2.20 J2.21 J2.24 J2.25 J2.28 J2.29 J2.32 J2.33 J2.37 J2.40 J2.41 J2.44 J2.45 J2.48 J2.49 J2.52 J2.56
SYS_24V: J1.56 J1.58 J1.60 J1.62 J1.64
24V_UNSWCH_BUS_CURRENT: J2.18 ; port 24V_UNSWCH_BUS_CURRENT
BAYCAT_3V3: J1.18 ; port BAYCAT_3V3
DIO_SPARE_0: J1.2 ; port DIO_SPARE_0
DIO_SPARE_1: J1.4 ; port DIO_SPARE_1
DIO_SPARE_2: J1.6 ; port DIO_SPARE_2
DIO_SPARE_3: J1.8 ; port DIO_SPARE_3
DIO_SPARE_4: J1.10 ; port DIO_SPARE_4
DIO_SPARE_5: J1.12 ; port DIO_SPARE_5
DIO_SPARE_6: J1.14 ; port DIO_SPARE_6
DIO_SPARE_7: J1.16 ; port DIO_SPARE_7
FAULT_MUX_A: J2.58 ; port FAULT_MUX_A
FAULT_MUX_B: J2.60 ; port FAULT_MUX_B
FAULT_MUX_C: J2.62 ; port FAULT_MUX_C
FAULT_SENSE_HCB: J2.55 ; port FAULT_SENSE_HCB
FAULT_SENSE_IPB1: J2.51
FAULT_SENSE_IPB2: J2.53
GF_AMP_TEMP_F: J2.59
GF_ANNODE_SEL_EN: J2.9
GF_CHASSIS_SEL_EN: J2.11
GF_SIG: J2.47
GF_SOURCE_SEL_A: J2.1
GF_SOURCE_SEL_B: J2.3
GF_SOURCE_SEL_C: J2.5
GF_SOURCE_SEL_ENn: J2.7
HCB_MEDIA_EN: J1.30 ; port HCB_MEDIA_EN
HPB_5V_CURRENT: J2.34 ; port HPB_5V_CURRENT
HPB_5V_VOLTAGE: J2.30 ; port HPB_5V_VOLTAGE
HPB_24V_CURRENT: J2.26 ; port HPB_24V_CURRENT
HPB_24V_VOLTAGE: J2.22 ; port HPB_24V_VOLTAGE
HPB_CISCO1_CURRENT: J2.2 ; port HPB_CISCO1_CURRENT
HPB_CISCO1_EN: J1.49 ; port HPB_CISCO1_EN
HPB_CISCO2_CURRENT: J2.6 ; port HPB_CISCO2_CURRENT
HPB_CISCO2_EN: J1.51 ; port HPB_CISCO2_EN
HPB_ISO24V_CURRENT: J2.14 ; port HPB_ISO24V_CURRENT
HPB_MEDIA_CURRENT: J2.64 ; port HPB_MEDIA_CURRENT
HPB_SYNCBOX_CURRENT: J2.10 ; port HPB_SYNCBOX_CURRENT
HPB_SYNCBOX_EN: J1.53 ; port HPB_SYNCBOX_EN
HPB_TEMP0: J1.44 ; port HPB_TEMP0_F
HPB_TEMP1: J1.46 ; port HPB_TEMP1_F
HPB_TEMP2: J1.48 ; port HPB_TEMP2_F
HPB_TEMP3: J1.50 ; port HPB_TEMP3_F
HPB_TEMP4: J1.52 ; port HPB_TEMP4_F
HPB_VICOR1_TEMP: J1.38 ; port HPB_VICOR1_TEMP_F
HPB_VICOR2_TEMP: J1.40 ; port HPB_VICOR2_TEMP_F
HPB_VICOR3_TEMP: J1.42 ; port HPB_VICOR3_TEMP_F
I2C_SCL: J1.26 ; port I2C_SCL
I2C_SDA: J1.22 ; port I2C_SDA
IGB1_CHA_FET_EN: J1.21
IGB1_CHA_RLY_EN: J1.17
IGB1_CHB_FET_EN: J1.29
IGB1_CHB_RLY_EN: J1.25
IGB1_CHC_FET_EN: J1.37
IGB1_CHC_RLY_EN: J1.33
IGB1_CHD_FET_EN: J1.45
IGB1_CHD_RLY_EN: J1.41
IGB2_CHA_FET_EN: J1.23
IGB2_CHA_RLY_EN: J1.19
IGB2_CHB_FET_EN: J1.31
IGB2_CHB_RLY_EN: J1.27
IGB2_CHC_FET_EN: J1.39
IGB2_CHC_RLY_EN: J1.35
IGB2_CHD_FET_EN: J1.47
IGB2_CHD_RLY_EN: J1.43
IGB_TEMP_F: J2.57
INPUT_FET_LEFT_TEMP_F: J2.63
INPUT_FET_RIGHT_TEMP_F: J2.61
IPB1_BOARD_TEMP: J1.34
IPB1_CHA_CURRENT_SET: J1.1
IPB1_CHA_I: J2.15
IPB1_CHB_CURRENT_SET: J1.5
IPB1_CHB_I: J2.23
IPB1_CHC_CURRENT_SET: J1.9
IPB1_CHC_I: J2.31
IPB1_CHD_CURRENT_SET: J1.13
IPB1_CHD_I: J2.39
IPB1_RESET: J2.36
IPB2_BOARD_TEMP: J1.36
IPB2_CHA_CURRENT_SET: J1.3
IPB2_CHA_I: J2.19
IPB2_CHB_CURRENT_SET: J1.7
IPB2_CHB_I: J2.27
IPB2_CHC_CURRENT_SET: J1.11
IPB2_CHC_I: J2.35
IPB2_CHD_CURRENT_SET: J1.15
IPB2_CHD_I: J2.43
IPB2_RESET: J2.38
MVC_L_CURRENT: J2.46
MVC_L_VOLTAGE: J2.54
MVC_R_CURRENT: J2.42
MVC_R_VOLTAGE: J2.50

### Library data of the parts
J1 J2 = CMP-002-00093-2: Conn Elevated Socket SKT 64 POS 2.54mm Solder ST Top Entry Thru-Hole Tube; Voltage Rating (AC): 550V; Current Rating: 6.9A; Number of Contacts: 64; Row Spacing: 0.1inch; Connector Type: Receptacle; Contact Resistance: 10mR

## Sheet 24V Isolation.SchDoc: MARS2 LVPS - HPB - ISO 24V
size 431 x 279 mm; Organization: ORGANIZATION; Address1: APPLIED PHYSICS LAB; Address2: UNIVERSITY OF WASHINGTON; Address3: 1013 NE 40TH STREET; Address4: SEATTLE, WA 98105; DocumentNumber: 5; Revision: -; SheetNumber: 6; SheetTotal: 15; ENG_APP_DATE: --/--/--; DSN_APP_DATE: --/--/--; CHK_APP_DATE: --/--/--
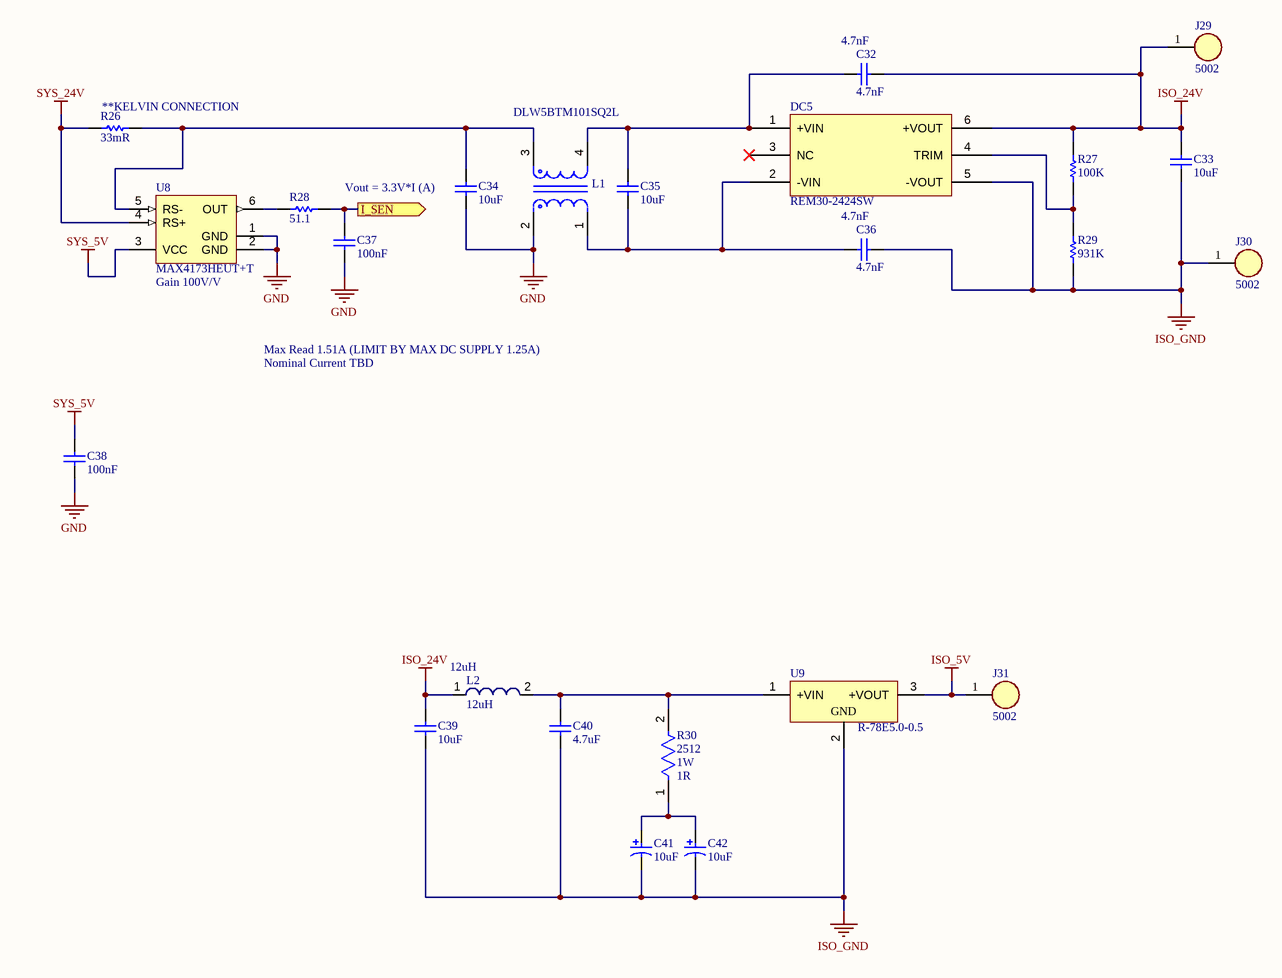
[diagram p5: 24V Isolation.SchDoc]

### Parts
C32  value 4.7nF  Capacitance: 4.7nF  [CAPC2013X145X50NL20T25]  (hidden comment: Capacitor 4.7nF 10%, 1kV, X7R, 0805)
C33  value 10uF  [CAPC3225X270X30ML30]  (hidden comment: Capacitor 10uF 10%, 50V, X7R, 1210)
C34  value 10uF  [CAPC3225X270X30ML30]  (hidden comment: Capacitor 10uF 10%, 50V, X7R, 1210)
C35  value 10uF  [CAPC3225X270X30ML30]  (hidden comment: Capacitor 10uF 10%, 50V, X7R, 1210)
C36  value 4.7nF  Capacitance: 4.7nF  [CAPC2013X145X50NL20T25]  (hidden comment: Capacitor 4.7nF 10%, 1kV, X7R, 0805)
C37  value 100nF  [CAPC1608X90X40NL10T20]  (hidden comment: Capacitor 100 nF +/-10% 50 V 0603)
C38  value 100nF  [CAPC1608X90X40NL10T20]  (hidden comment: Capacitor 100 nF +/-10% 50 V 0603)
C39  value 10uF  [CAPC3225X270X30ML30]  (hidden comment: Capacitor 10uF 10%, 50V, X7R, 1210)
C40  value 4.7uF  [CAPC3225X270X30ML30]  (hidden comment: Capacitor 4.7uF 10%, 50V, X7R, 1210)
C41  value 10uF  [KEMT-D-7343-31-2_L]  (hidden comment: T491D106K050AT)
C42  value 10uF  [KEMT-D-7343-31-2_L]  (hidden comment: T491D106K050AT)
DC5  REM30-2424SW  [REM30-2424SW-Footprint-1]
J29  5002  [FP-5002-MFG]
J30  5002  [FP-5002-MFG]
J31  5002  [FP-5002-MFG]
L1  DLW5BTM101SQ2L  [FP-DLW5BT-MFG]
L2  value 12uH  Inductance: 12uH  [WE-LQS 8040]  (hidden comment: 74404084120)
R26  Resistance: 33mR  [RESC3216X70X50NL05T20]  (hidden comment: Resistor 0R033 1% 1206 1W)
R27  value 100K  [RESC1609X50X30ML08T20]  (hidden comment: Resistor 100K +/-1% 0603 100 mW)
R28  value 51.1  [RESC1609X50X30ML08T20]  (hidden comment: Resistor 51R1 +/-1% 0603 100 mW)
R29  value 931K  [RESC1609X50X30ML08T20]  (hidden comment: Resistor 931K +/-1% 0603 100 mW)
R30  Case Code (Imperial): 2512  Power Rating: 1W  Resistance: 1R  [FP-CRCW2512-e3-MFG]  (hidden comment: Resistor 1R0 1% 2512 1W)
U8  MAX4173HEUT+T  [MAXM-U6+1_N]
U9  R-78E5.0-0.5  [REPO-R-78E-0.5-3_V]

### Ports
I_SEN (out)

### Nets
GND: C34.1 C37.1 C38.1 L1.2 U8.1(GND) U8.2(GND)
ISO_5V: J31.1 U9.3(+VOUT)
ISO_24V: C32.2 C33.2 C39.2 DC5.6(+VOUT) J29.1 L2.1 R27.2
ISO_GND: C33.1 C36.2 C39.1 C40.1 C41.2 C42.2 DC5.5(-VOUT) J30.1 R29.1 U9.2(GND)
SYS_5V: C38.2 U8.3(VCC)  [project net VCC]
SYS_24V: R26.2 U8.4(RS+)
HPB_ISO24V_CURRENT: C37.2 R28.2 ; port I_SEN
NetC32_1: C32.1 C35.2 DC5.1(+VIN) L1.4
NetC34_2: C34.2 L1.3 R26.1 U8.5(RS-)
NetC35_1: C35.1 C36.1 DC5.2(-VIN) L1.1
NetC40_2: C40.2 L2.2 R30.2 U9.1(+VIN)
NetC41_1: C41.1 C42.1 R30.1
NetDC5_4: DC5.4(TRIM) R27.1 R29.2
NetR28_1: R28.1 U8.6(OUT)

Not connected (* = marked no-connect by the designer): DC5 3(NC)*

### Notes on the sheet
- (near R26) **KELVIN CONNECTION
- Vout = 3.3V*I (A)
- (near U8) Gain 100V/V
- Nominal Current TBD
- Max Read 1.51A (LIMIT BY MAX DC SUPPLY 1.25A)

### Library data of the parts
C32 C36 = CMP-001-00109-9: as C1 on sheet 24V Power Bus Supply
C33-C35 C39 = CMP-001-00184-9: Chip Capacitor, 10uF, 10%, 50 V, X7R 1210 (3225 Metric); Capacitor Type: Ceramic
C37 C38 = CMP-001-00017-14: as C13 on sheet 24V Power Bus Supply
C40 = CMP-001-00183-9: Chip Capacitor, 4.7uF, 10%, 50 V, X7R 1210 (3225 Metric); Capacitor Type: Ceramic; Decade: 1uF
C41 C42 = CMP-001-00088-9: 10uF Solid MnO2 Tantalum Electrolytic Capacitor; 50 V dc +/-10%; T491 Series; Manufacturer: KEMET; Voltage: 50V; Tolerance: 10%; Life (Hours): 2000Hour; Dissipation Factor: 6%; Ripple Current: 433mA; Leakage Current: 5uA; ESR (Equivalent Series Resistance): 800mR; Polarity: Polar
DC5 = CMP-019-00061-2: 30W DC/DC-Converter 'MEDLINE' 2"x1" 5kV reg 4: 1; Voltage - Input (Max): 36V; Current - Output (Max): 1.25A; Voltage - Input (Min): 9V; Voltage - Output 1: 24V; Efficiency: 89%
J29-J31 = CMP-002-00083-3: as J19 on sheet IGB Power Connector
L1 = CMP-006-00027-1: Ind Common Mode Choke Wirewound 100 Ohm 100MHz 6A 2020 Embossed T/R; Number of Lines: 2; DC Resistance (DCR): 13mR; Impedance: 100R; Voltage Rating (DC): 50V; Shielding: Unshielded; Tolerance: 40%
L2 = CMP-006-00026-2: WE-LQS Series; Shielded Wire-wound SMD Inductor 12; RMS Current (Irms): 2.8A; Saturation Current: 3.8A; DC Resistance (DCR): 40mR; Tolerance: 20%; Core Material: Ferrite; Self Resonant Frequency: 21MHz; Test Frequency: 100kHz
R26 = CMP-009-01194-1: Res Thick Film 1206 0.033 Ohm 1% 1W ±75ppm/C Pad SMD Automotive T/R; Manufacturer PN: ERJ-8CWFR033V; Temperature Coefficient: 75ppm/°C
R27 = CMP-009-01065-1: Chip Resistor, 100k Ohm, +/- 1%, 0.1 W, -55 to 155 degC, 0603 (1608 Metric); Power: 100mW; Voltage Rating: 75V
R28 = CMP-009-01135-1: as R22 on sheet 24V Power Bus Supply
R29 = CMP-009-01062-1: Chip Resistor, 931k Ohm, +/- 1%, 0.1 W, -55 to 155 degC, 0603 (1608 Metric); Power: 100mW; Decade: 100k; Voltage Rating: 75V
R30 = CMP-009-01195-2: Res Thick Film 2512 1 Ohm 1% 1W ±100ppm/°C Molded SMD SMD; Manufacture PN: CRCW25121R00FKEG; Voltage Rating: 500V
U8 = CMP-014-00008-1: MAX4173 Series 28 V 1.2 MHz Voltage Current Sense Operational Amplifier - SOT-23; Gain: 100V/V; Common Mode Rejection Ratio: 90dB; Max Supply Voltage: 28V; -3db Bandwidth: 1.2MHz; Supply Current: 420uA; Min Supply Voltage: 3V; Input Bias Current: 700uA
U9 = CMP-019-00059-1: 0.5A DC/DC-Converter 'INNOLINE' SIP3 reg; V. In: 7-28; V. Out: 5.0; mA. Out: 500; Max Power Dissipation: 3W; Max Input Voltage: 28V; Current - Output 1: 500mA; Power Rating: 2.5W; Output Voltage: 5V; Min Input Voltage: 7V; Isolation: Non-Isolated; Number of Outputs: 1; Efficiency: 92%; Output Type: Fixed

## Sheet 5V_POWER_SUPPLY.SchDoc: MARS2 LVPS - HPB - 5V PSU
size 431 x 279 mm; Organization: ORGANIZATION; Address1: APPLIED PHYSICS LAB; Address2: UNIVERSITY OF WASHINGTON; Address3: 1013 NE 40TH STREET; Address4: SEATTLE, WA 98105; DocumentNumber: 6; Revision: -; SheetNumber: 7; SheetTotal: 15; ENG_APP_DATE: --/--/--; DSN_APP_DATE: --/--/--; CHK_APP_DATE: --/--/--
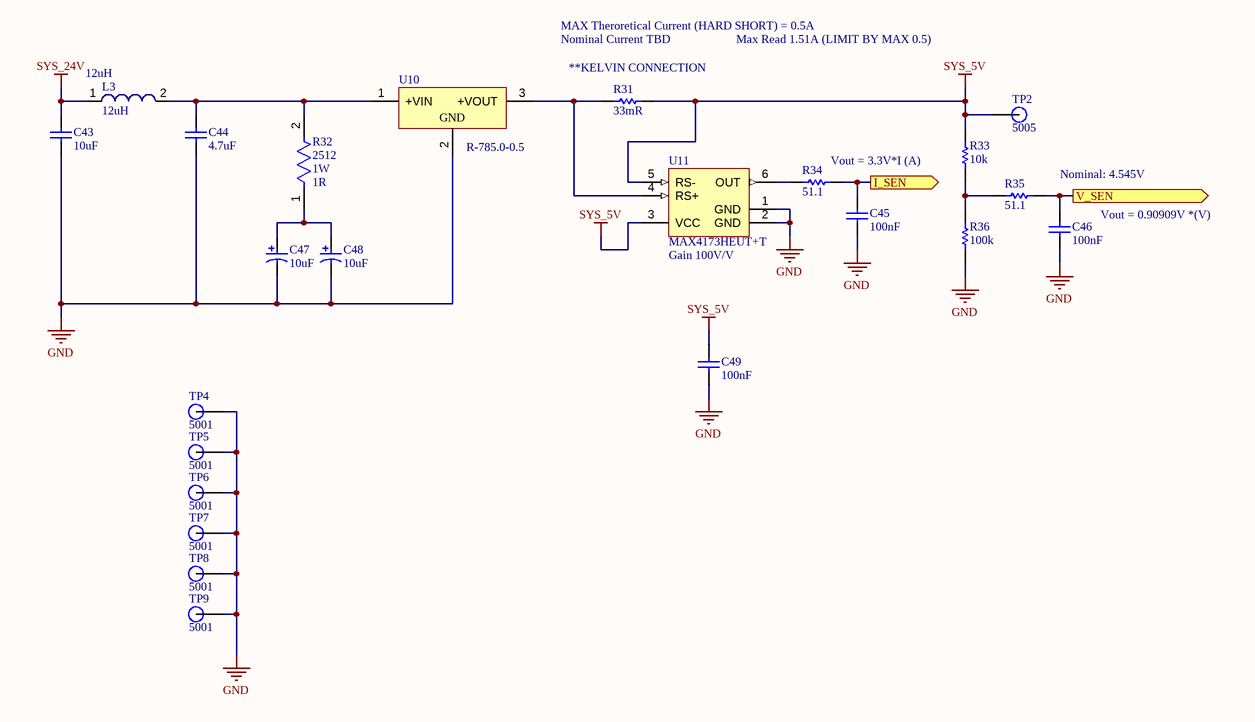
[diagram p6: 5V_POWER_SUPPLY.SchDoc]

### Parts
C43  value 10uF  [CAPC3225X270X30ML30]  (hidden comment: Capacitor 10uF 10%, 50V, X7R, 1210)
C44  value 4.7uF  [CAPC3225X270X30ML30]  (hidden comment: Capacitor 4.7uF 10%, 50V, X7R, 1210)
C45  value 100nF  [CAPC1608X90X40NL10T20]  (hidden comment: Capacitor 100 nF +/-10% 50 V 0603)
C46  value 100nF  [CAPC1608X90X40NL10T20]  (hidden comment: Capacitor 100 nF +/-10% 50 V 0603)
C47  value 10uF  [KEMT-D-7343-31-2_L]  (hidden comment: T491D106K050AT)
C48  value 10uF  [KEMT-D-7343-31-2_L]  (hidden comment: T491D106K050AT)
C49  value 100nF  [CAPC1608X90X40NL10T20]  (hidden comment: Capacitor 100 nF +/-10% 50 V 0603)
L3  value 12uH  Inductance: 12uH  [WE-LQS 8040]  (hidden comment: 74404084120)
R31  Resistance: 33mR  [RESC3216X70X50NL05T20]  (hidden comment: Resistor 0R033 1% 1206 1W)
R32  Case Code (Imperial): 2512  Power Rating: 1W  Resistance: 1R  [FP-CRCW2512-e3-MFG]  (hidden comment: Resistor 1R0 1% 2512 1W)
R33  value 10k  [RESC1608X55X25ML10T15]  (hidden comment: Resistor 10k +/-1% 0603 100 mW)
R34  value 51.1  [RESC1609X50X30ML08T20]  (hidden comment: Resistor 51R1 +/-1% 0603 100 mW)
R35  value 51.1  [RESC1609X50X30ML08T20]  (hidden comment: Resistor 51R1 +/-1% 0603 100 mW)
R36  value 100k  [RESC1608X55X25ML10T15]  (hidden comment: Resistor 100k +/-1% 0603 100 mW)
TP2  5005  [TestPoint-5005-Footprint-1]
TP4  5001  [FP-5001-MFG]
TP5  5001  [FP-5001-MFG]
TP6  5001  [FP-5001-MFG]
TP7  5001  [FP-5001-MFG]
TP8  5001  [FP-5001-MFG]
TP9  5001  [FP-5001-MFG]
U10  R-785.0-0.5  [REPO-R-78XX-3_V]
U11  MAX4173HEUT+T  [MAXM-U6+1_N]

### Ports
I_SEN (out), V_SEN (out)

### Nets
GND: C43.1 C44.1 C45.1 C46.1 C47.2 C48.2 C49.1 R36.1 TP4.1 TP5.1 TP6.1 TP7.1 TP8.1 TP9.1 U10.2(GND) U11.1(GND) U11.2(GND)
SYS_5V: C49.2 R31.1 R33.2 TP2.1 U11.3(VCC) U11.5(RS-)  [project net VCC]
SYS_24V: C43.2 L3.1
HPB_5V_CURRENT: C45.2 R34.2 ; port I_SEN
HPB_5V_VOLTAGE: C46.2 R35.2 ; port V_SEN
NetC44_2: C44.2 L3.2 R32.2 U10.1(+VIN)
NetC47_1: C47.1 C48.1 R32.1
NetR31_2: R31.2 U10.3(+VOUT) U11.4(RS+)
NetR33_1: R33.1 R35.1 R36.2
NetR34_1: R34.1 U11.6(OUT)

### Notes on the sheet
- MAX Theroretical Current (HARD SHORT) = 0.5A
- Nominal Current TBD
- Max Read 1.51A (LIMIT BY MAX 0.5)
- (near R31) **KELVIN CONNECTION
- (near R34) Vout = 3.3V*I (A)
- Nominal: 4.545V
- (near U11) Gain 100V/V
- (near C46) Vout = 0.90909V *(V)

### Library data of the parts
C43 = CMP-001-00184-9: as C33 on sheet 24V Isolation
C44 = CMP-001-00183-9: as C40 on sheet 24V Isolation
C45 C46 C49 = CMP-001-00017-14: as C13 on sheet 24V Power Bus Supply
C47 C48 = CMP-001-00088-9: as C41 on sheet 24V Isolation
L3 = CMP-006-00026-2: as L2 on sheet 24V Isolation
R31 = CMP-009-01194-1: as R26 on sheet 24V Isolation
R32 = CMP-009-01195-2: as R30 on sheet 24V Isolation
R33 = CMP-009-00017-7: as R24 on sheet 24V Power Bus Supply
R34 R35 = CMP-009-01135-1: as R22 on sheet 24V Power Bus Supply
R36 = CMP-009-00023-6: Chip Resistor, 100 KOhm, +/- 1%, 0.1 W, -55 to 155 degC, 0603 (1608 Metric); Voltage Rating: 50V; Power: 100mW
TP2 = CMP-001-0000-5: as TP1 on sheet 24V Power Bus Supply
TP4-TP9 = CMP-001-0002-3: TEST POINT PC MINI .040D BLACK
U10 = CMP-019-00062-2: 0.5A DC/DC-Converter 'INNOLINE' SIP3 reg; V. In: 6.5-32; V. Out: 5.0; mA. Out: 500; Nominal Input Voltage: 24V; Max Power Dissipation: 3W; Efficiency: 94%; Min Input Voltage (DC): 6.5V; Current - Output 1: 500mA; Isolation: Non-Isolated; Max Input Voltage: 32V; Switching Frequency: 380kHz; Max Output Power: 2.5W; Max Output Voltage: 5V; Isolation Voltage: 2kV
U11 = CMP-014-00008-1: as U8 on sheet 24V Isolation

## Sheet MVC Connector.SchDoc: MARS2 LVPS - HPB - MVC Conn
size 431 x 279 mm; Organization: ORGANIZATION; Address1: APPLIED PHYSICS LAB; Address2: UNIVERSITY OF WASHINGTON; Address3: 1013 NE 40TH STREET; Address4: SEATTLE, WA 98105; DocumentNumber: 7; Revision: -; SheetNumber: 8; SheetTotal: 15; ENG_APP_DATE: --/--/--; DSN_APP_DATE: --/--/--; CHK_APP_DATE: --/--/--
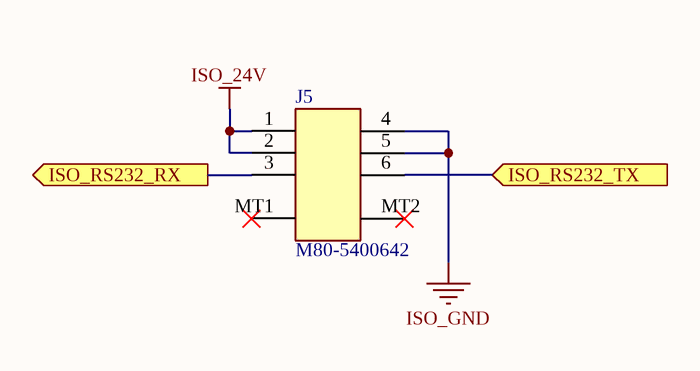
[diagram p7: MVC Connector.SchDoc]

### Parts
J5  M80-5400642  [FP-M80-5400642-MFG]

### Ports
ISO_RS232_RX (out), ISO_RS232_TX (in)

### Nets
ISO_24V: J5.1 J5.2
ISO_GND: J5.4 J5.5
NetJ5_3: J5.3 ; port ISO_RS232_RX
NetJ5_6: J5.6 ; port ISO_RS232_TX

Not connected (* = marked no-connect by the designer): J5 MT1* MT2*

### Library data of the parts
J5 = CMP-002-00076-5: Conn Header R/a 6POS 2MM; Manufacturer: Harwin; Current Rating: 3A; Contact Resistance: 25mR; Gender: Male; Max Voltage Rating (AC): 120V; Voltage Rating: 800V; Number of Contacts: 6; Insulation Resistance: 100MR

## Sheet Output Connectors.SchDoc: MARS2 LVPS - HPB - Output Connectors
size 431 x 279 mm; Organization: ORGANIZATION; Address1: APPLIED PHYSICS LAB; Address2: UNIVERSITY OF WASHINGTON; Address3: 1013 NE 40TH STREET; Address4: SEATTLE, WA 98105; DocumentNumber: 10; Revision: -; SheetNumber: 12; SheetTotal: 15; ENG_APP_DATE: --/--/--; DSN_APP_DATE: --/--/--; CHK_APP_DATE: --/--/--
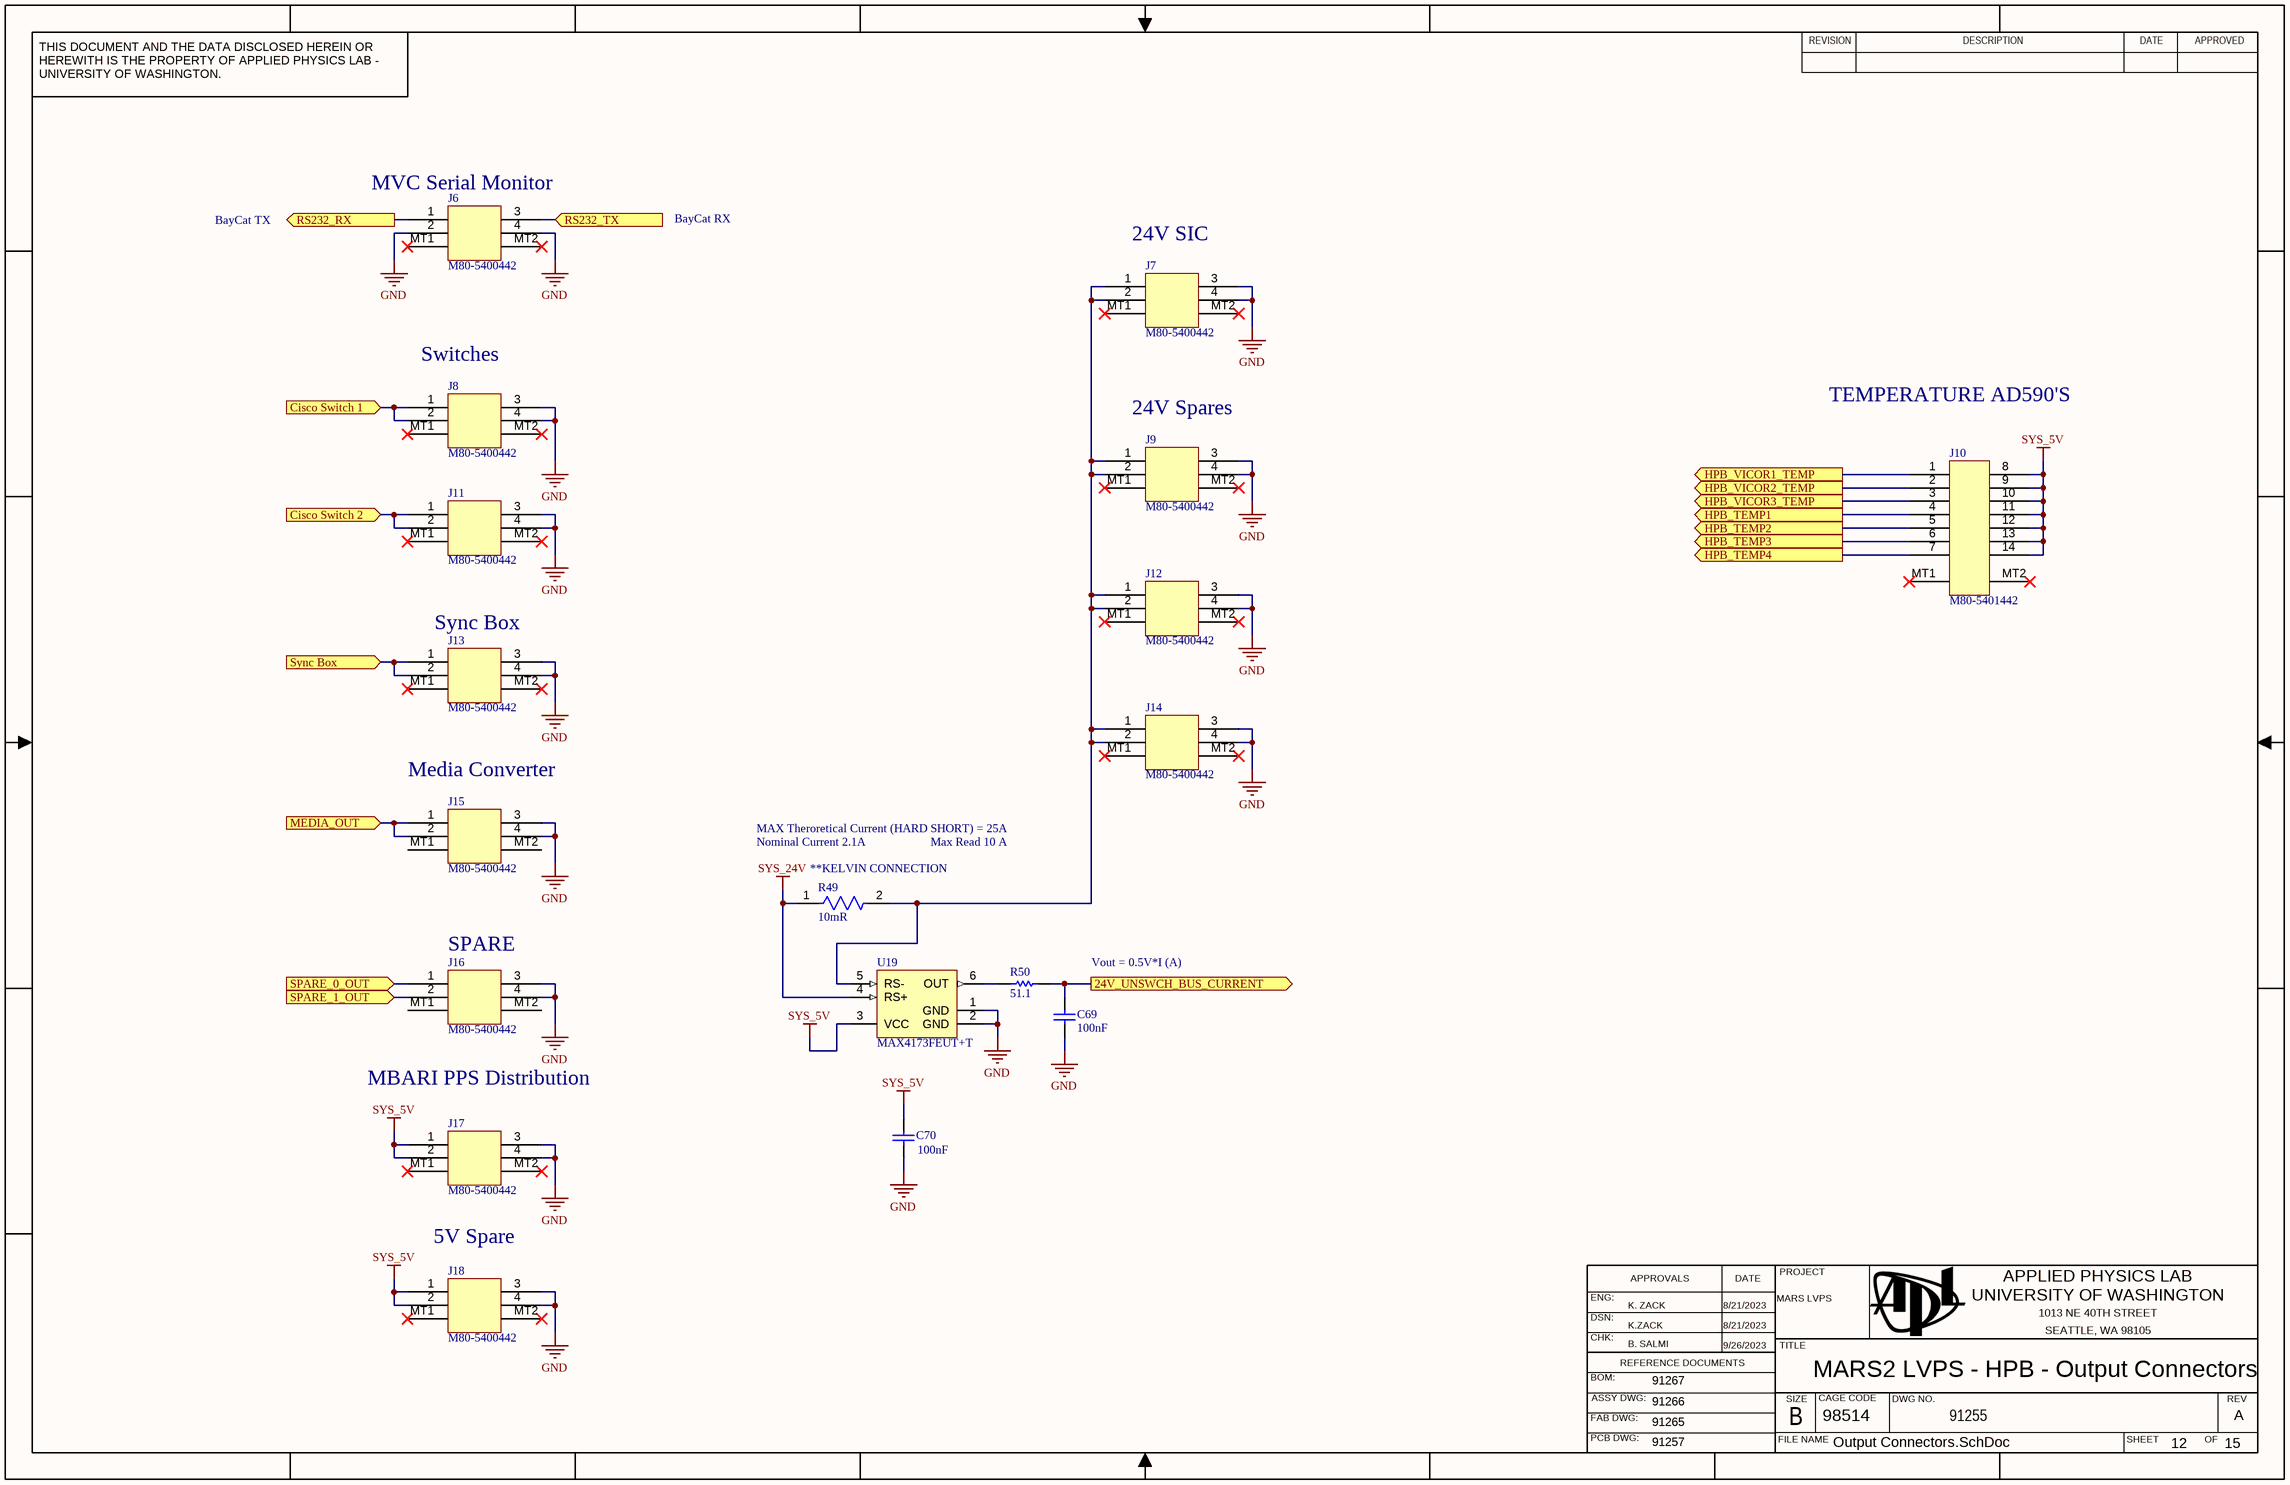
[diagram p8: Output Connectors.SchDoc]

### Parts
C69  value 100nF  [CAPC1608X90X40NL10T20]  (hidden comment: Capacitor 100 nF +/-10% 50 V 0603)
C70  value 100nF  [CAPC1608X90X40NL10T20]  (hidden comment: Capacitor 100 nF +/-10% 50 V 0603)
J6  M80-5400442  [M80-5400442-Footprint-1]
J7  M80-5400442  [M80-5400442-Footprint-1]
J8  M80-5400442  [M80-5400442-Footprint-1]
J9  M80-5400442  [M80-5400442-Footprint-1]
J10  M80-5401442  [M80-5401442-Footprint-1]
J11  M80-5400442  [M80-5400442-Footprint-1]
J12  M80-5400442  [M80-5400442-Footprint-1]
J13  M80-5400442  [M80-5400442-Footprint-1]
J14  M80-5400442  [M80-5400442-Footprint-1]
J15  M80-5400442  [M80-5400442-Footprint-1]
J16  M80-5400442  [M80-5400442-Footprint-1]
J17  M80-5400442  [M80-5400442-Footprint-1]
J18  M80-5400442  [M80-5400442-Footprint-1]
R49  Resistance: 10mR  [FP-WSLP1206-FP_1_65x1_93x-IPC_A]  (hidden comment: Resistor 0R01 1% 1206 1W)
R50  value 51.1  [RESC1609X50X30ML08T20]  (hidden comment: Resistor 51R1 +/-1% 0603 100 mW)
U19  MAX4173FEUT+T  [MAXM-U6+1_N]

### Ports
24V_UNSWCH_BUS_CURRENT (out), Cisco Switch 1 (in), Cisco Switch 2 (in), HPB_TEMP1 (out), HPB_TEMP2 (out), HPB_TEMP3 (out), HPB_TEMP4 (out), HPB_VICOR1_TEMP (out), HPB_VICOR2_TEMP (out), HPB_VICOR3_TEMP (out), MEDIA_OUT (in), RS232_RX (out), RS232_TX (in), SPARE_0_OUT (in), SPARE_1_OUT (in), Sync Box (in)

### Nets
GND: C69.1 C70.1 J6.2 J6.4 J7.3 J7.4 J8.3 J8.4 J9.3 J9.4 J11.3 J11.4 J12.3 J12.4 J13.3 J13.4 J14.3 J14.4 J15.3 J15.4 J16.3 J16.4 J17.3 J17.4 J18.3 J18.4 U19.1(GND) U19.2(GND)
SYS_5V: C70.2 J10.8 J10.9 J10.10 J10.11 J10.12 J10.13 J10.14 J17.1 J17.2 J18.1 J18.2 U19.3(VCC)  [project net VCC]
SYS_24V: R49.1 U19.4(RS+)
24V_UNSWCH_BUS_CURRENT: C69.2 R50.2 ; port 24V_UNSWCH_BUS_CURRENT
NetJ6_1: J6.1 ; port RS232_RX
NetJ6_3: J6.3 ; port RS232_TX
NetJ7_1: J7.1 J7.2 J9.1 J9.2 J12.1 J12.2 J14.1 J14.2 R49.2 U19.5(RS-)
NetJ8_1: J8.1 J8.2 ; port Cisco Switch 1
NetJ10_1: J10.1 ; port HPB_VICOR1_TEMP
NetJ10_2: J10.2 ; port HPB_VICOR2_TEMP
NetJ10_3: J10.3 ; port HPB_VICOR3_TEMP
NetJ10_4: J10.4 ; port HPB_TEMP1
NetJ10_5: J10.5 ; port HPB_TEMP2
NetJ10_6: J10.6 ; port HPB_TEMP3
NetJ10_7: J10.7 ; port HPB_TEMP4
NetJ11_1: J11.1 J11.2 ; port Cisco Switch 2
NetJ13_1: J13.1 J13.2 ; port Sync Box
NetJ15_1: J15.1 J15.2 ; port MEDIA_OUT
NetJ16_1: J16.1 ; port SPARE_0_OUT
NetJ16_2: J16.2 ; port SPARE_1_OUT
NetR50_1: R50.1 U19.6(OUT)

Not connected (* = marked no-connect by the designer): J6 MT1* MT2*; J7 MT1* MT2*; J8 MT1* MT2*; J9 MT1* MT2*; J10 MT1* MT2*; J11 MT1* MT2*; J12 MT1* MT2*; J13 MT1* MT2*; J14 MT1* MT2*; J15 MT1 MT2; J16 MT1 MT2; J17 MT1* MT2*; J18 MT1* MT2*

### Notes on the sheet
- BayCat TX
- (near J6) MVC Serial Monitor
- BayCat RX
- (near J7) 24V SIC
- (near J8) Switches
- (near J9) 24V Spares
- TEMPERATURE AD590'S
- (near J13) Sync Box
- (near J15) Media Converter
- MAX Theroretical Current (HARD SHORT) = 25A
- Nominal Current 2.1A
- (near R49) **KELVIN CONNECTION
- Max Read 10 A
- (near J16) SPARE
- Vout = 0.5V*I (A)
- MBARI PPS Distribution
- 5V Spare

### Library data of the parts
C69 C70 = CMP-001-00017-14: as C13 on sheet 24V Power Bus Supply
J6-J9 J11-J18 = CMP-002-00095-3: HARWIN - M80-5400442 - Wire-To-Board Connector, 2 mm, 4 Contacts, Header, Datamate J-Tek M80 Series, Through Hole, 2 Rows; Number of Positions: 4; Maximum Voltage: 800V; Gender: Male; Pitch: 2mm; Current Rating: 2.2A; Contact Resistance: 25mR; Insulation Resistance: 100MR
J10 = CMP-002-00100-2: Conn Datamate M 14 POS 2mm Solder RA Thru-Hole Tube; Manufacturer: Harwin; Gender: Male; Number of Contacts: 14; Voltage Rating: 800V; Max Current Rating: 3A; Connector Type: Header; Contact Resistance: 25mR
R49 = CMP-009-01193-1: as R19 on sheet 24V Power Bus Supply
R50 = CMP-009-01135-1: as R22 on sheet 24V Power Bus Supply
U19 = CMP-014-00007-3: as U6 on sheet 24V Power Bus Supply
